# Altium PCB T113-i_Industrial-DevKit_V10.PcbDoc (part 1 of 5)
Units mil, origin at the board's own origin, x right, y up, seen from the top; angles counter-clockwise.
Board outline 4212.61 x 3188.98 mil, 4 copper layers (Top Layer, GND, PWR, Bottom Layer); 249 components, 236 nets, 911 pads, 571 vias.
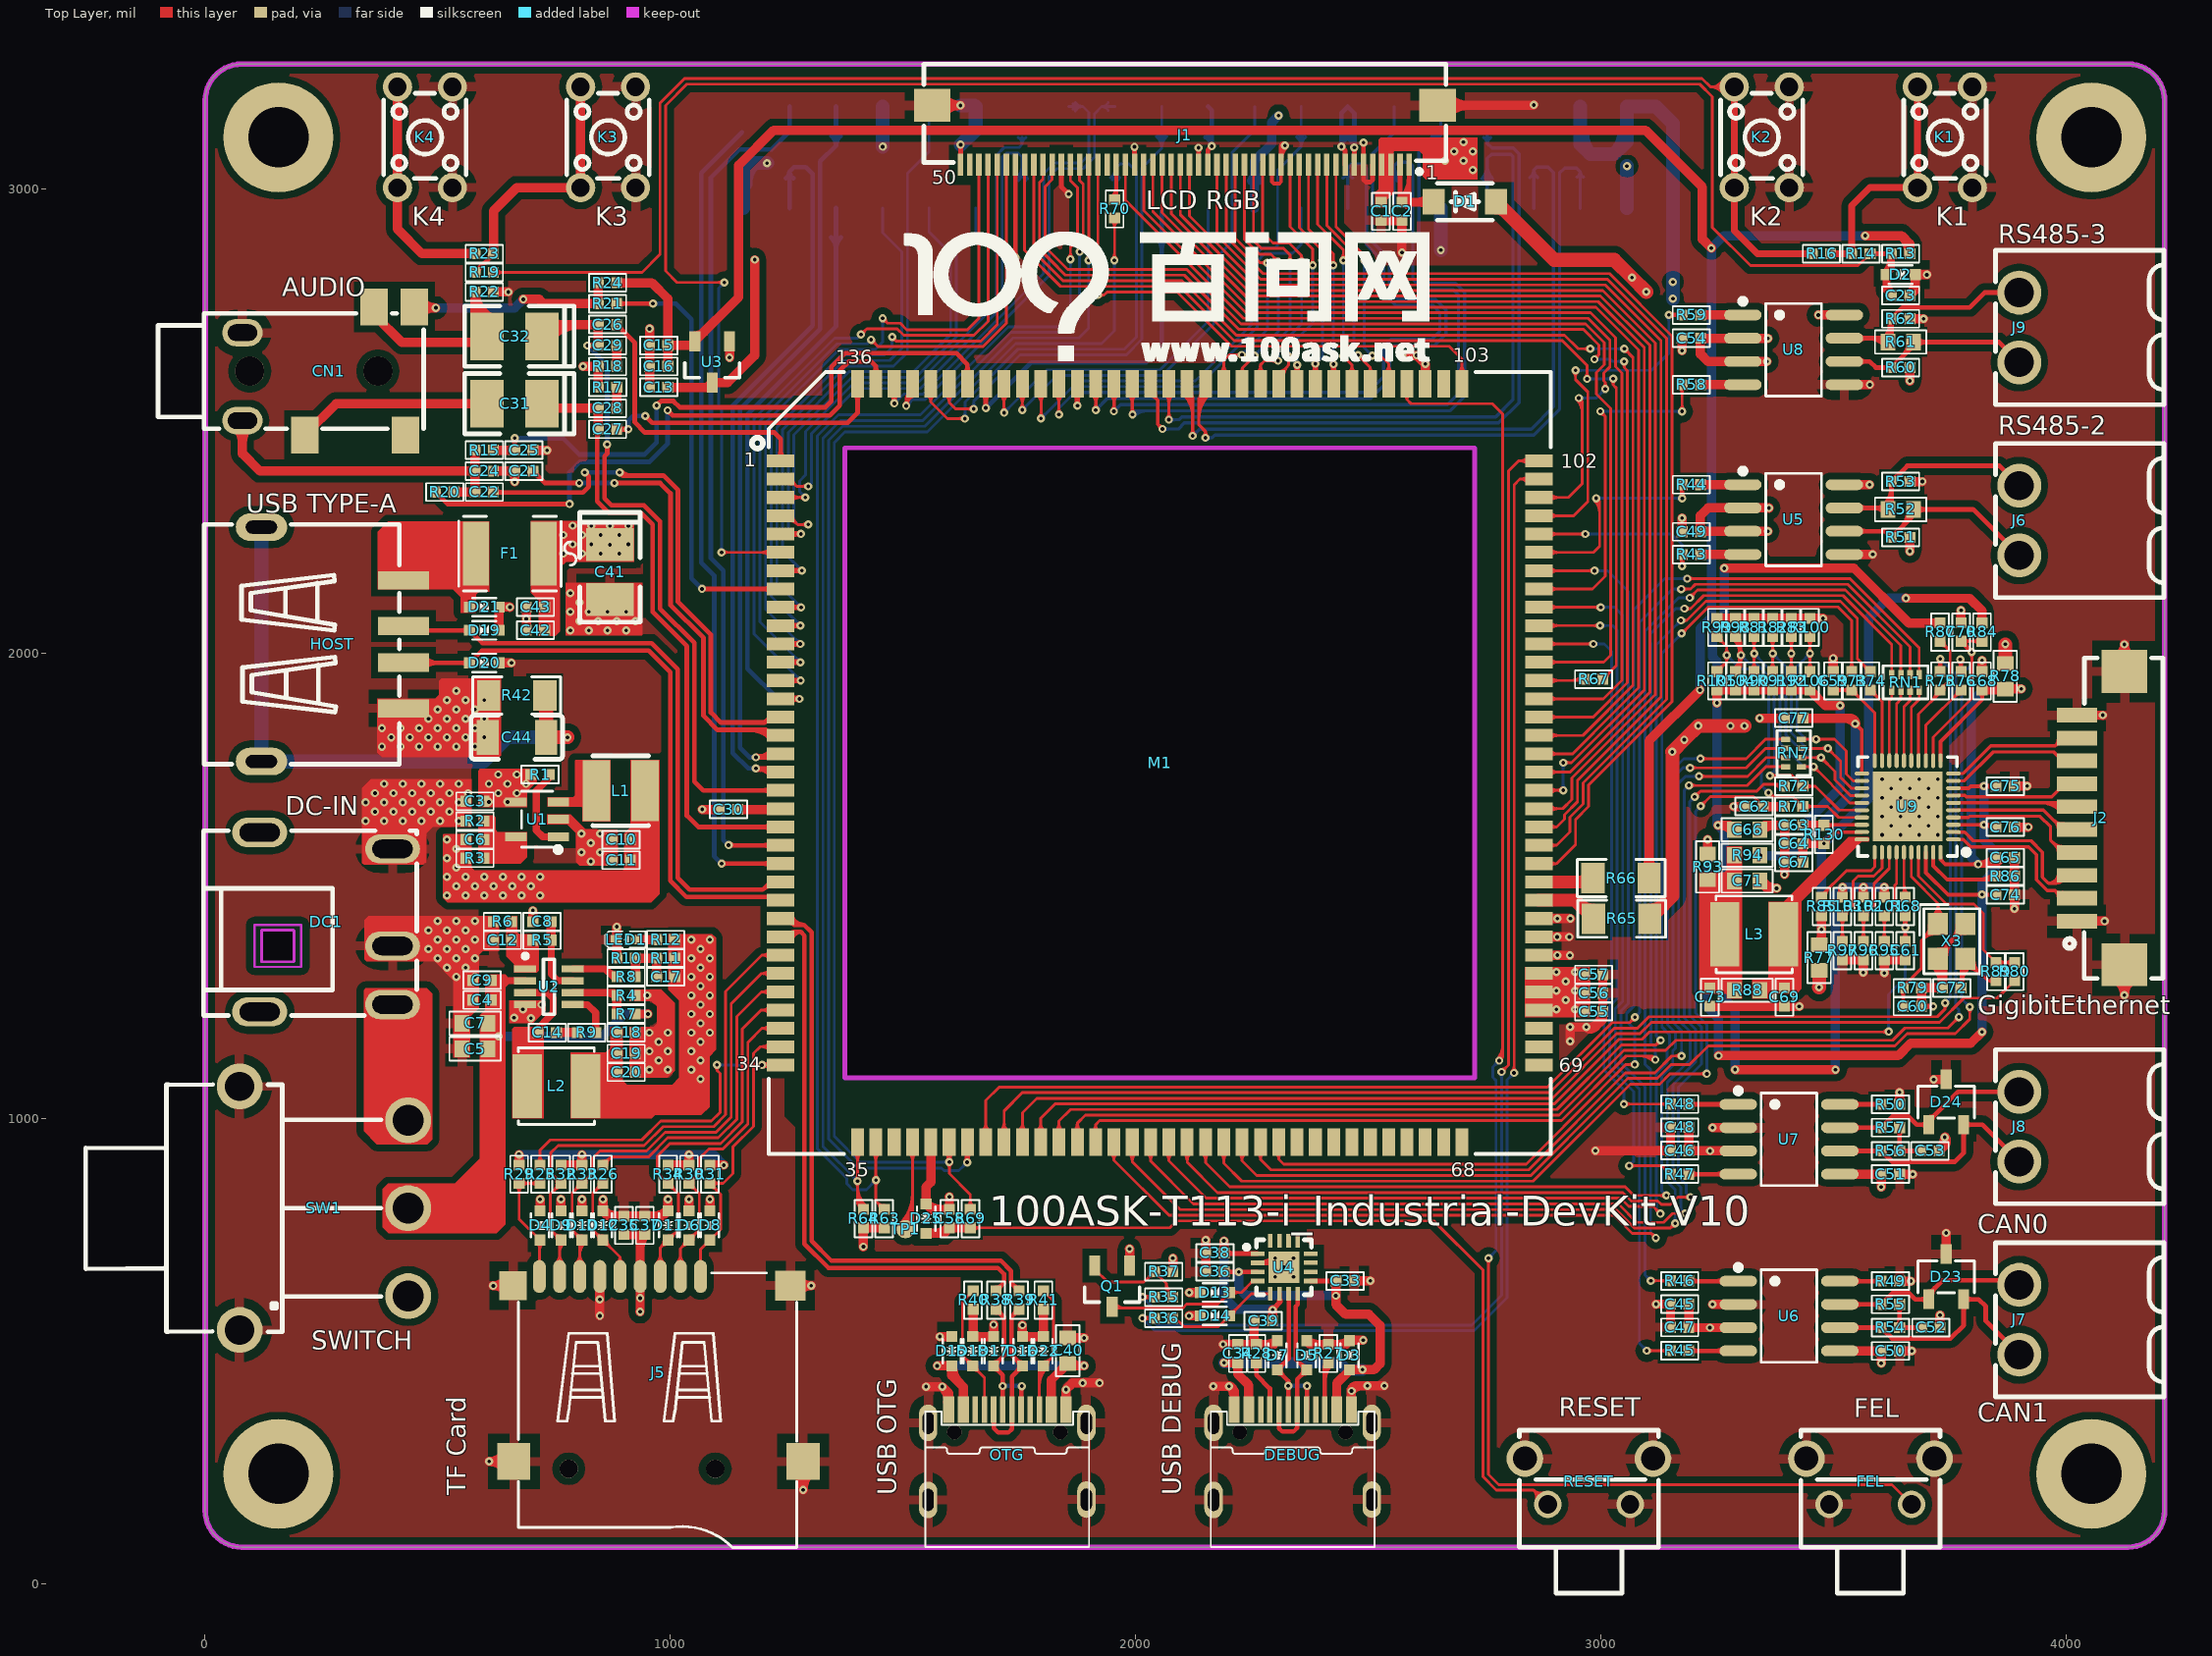
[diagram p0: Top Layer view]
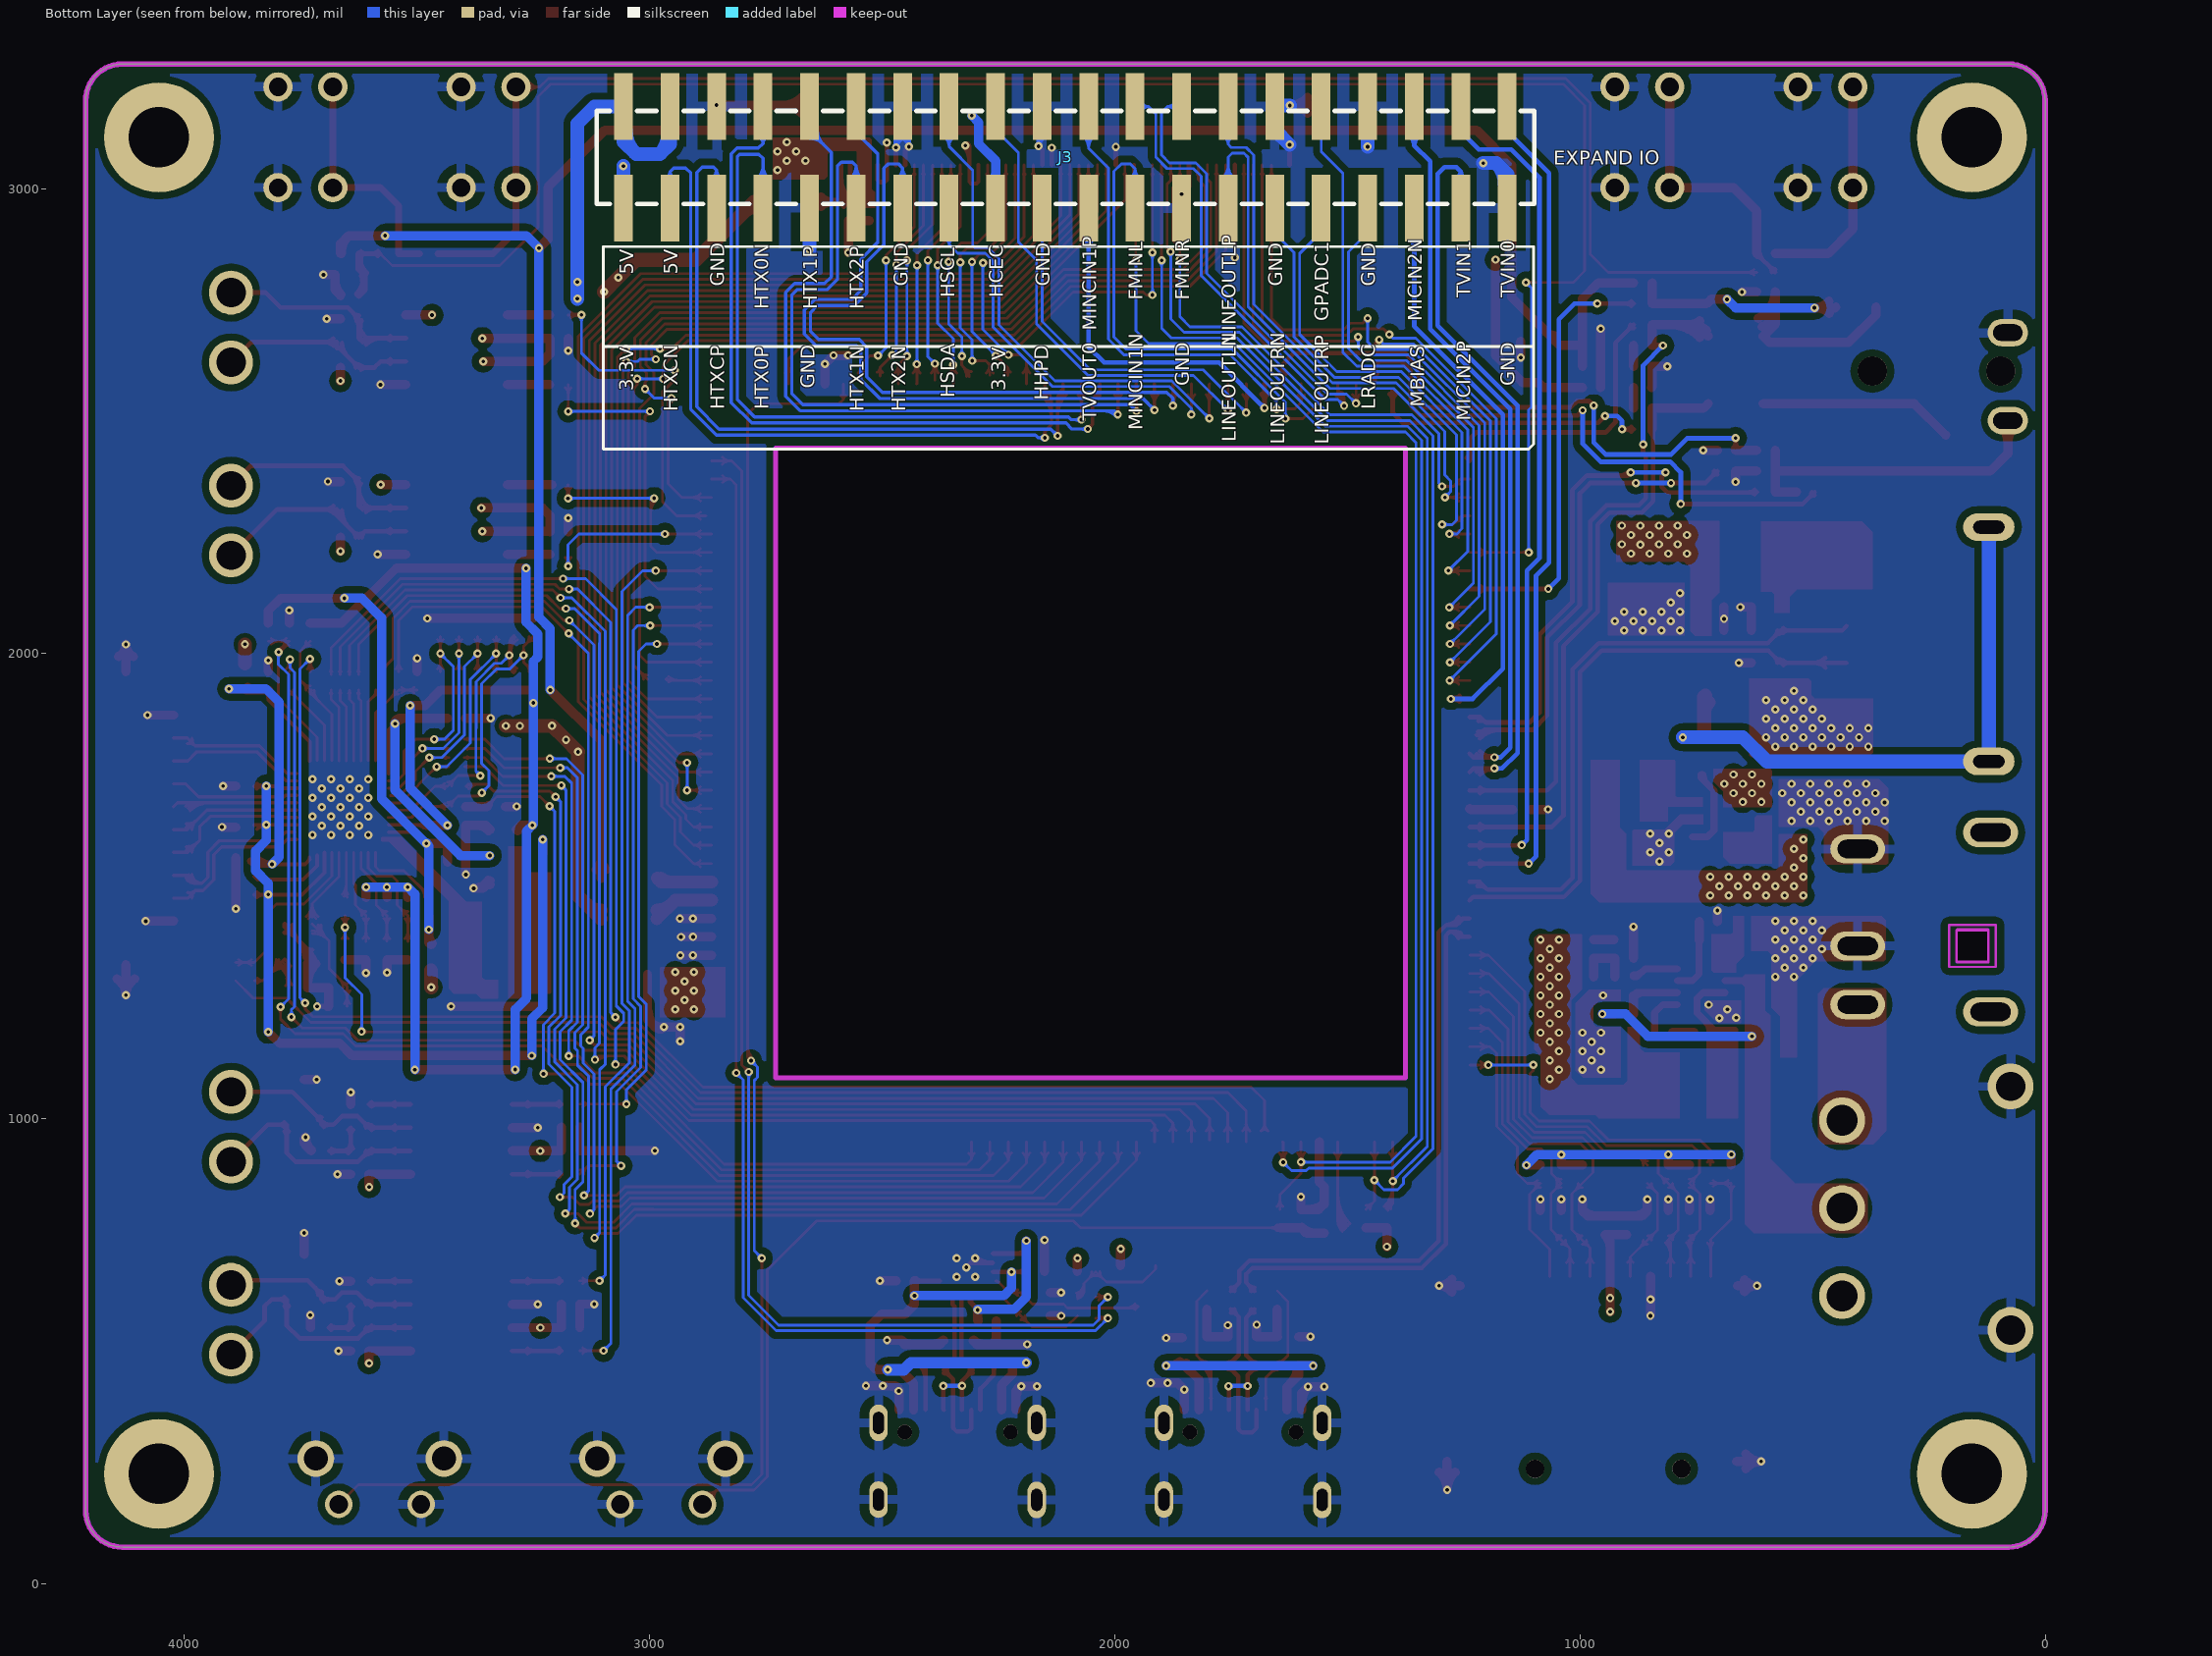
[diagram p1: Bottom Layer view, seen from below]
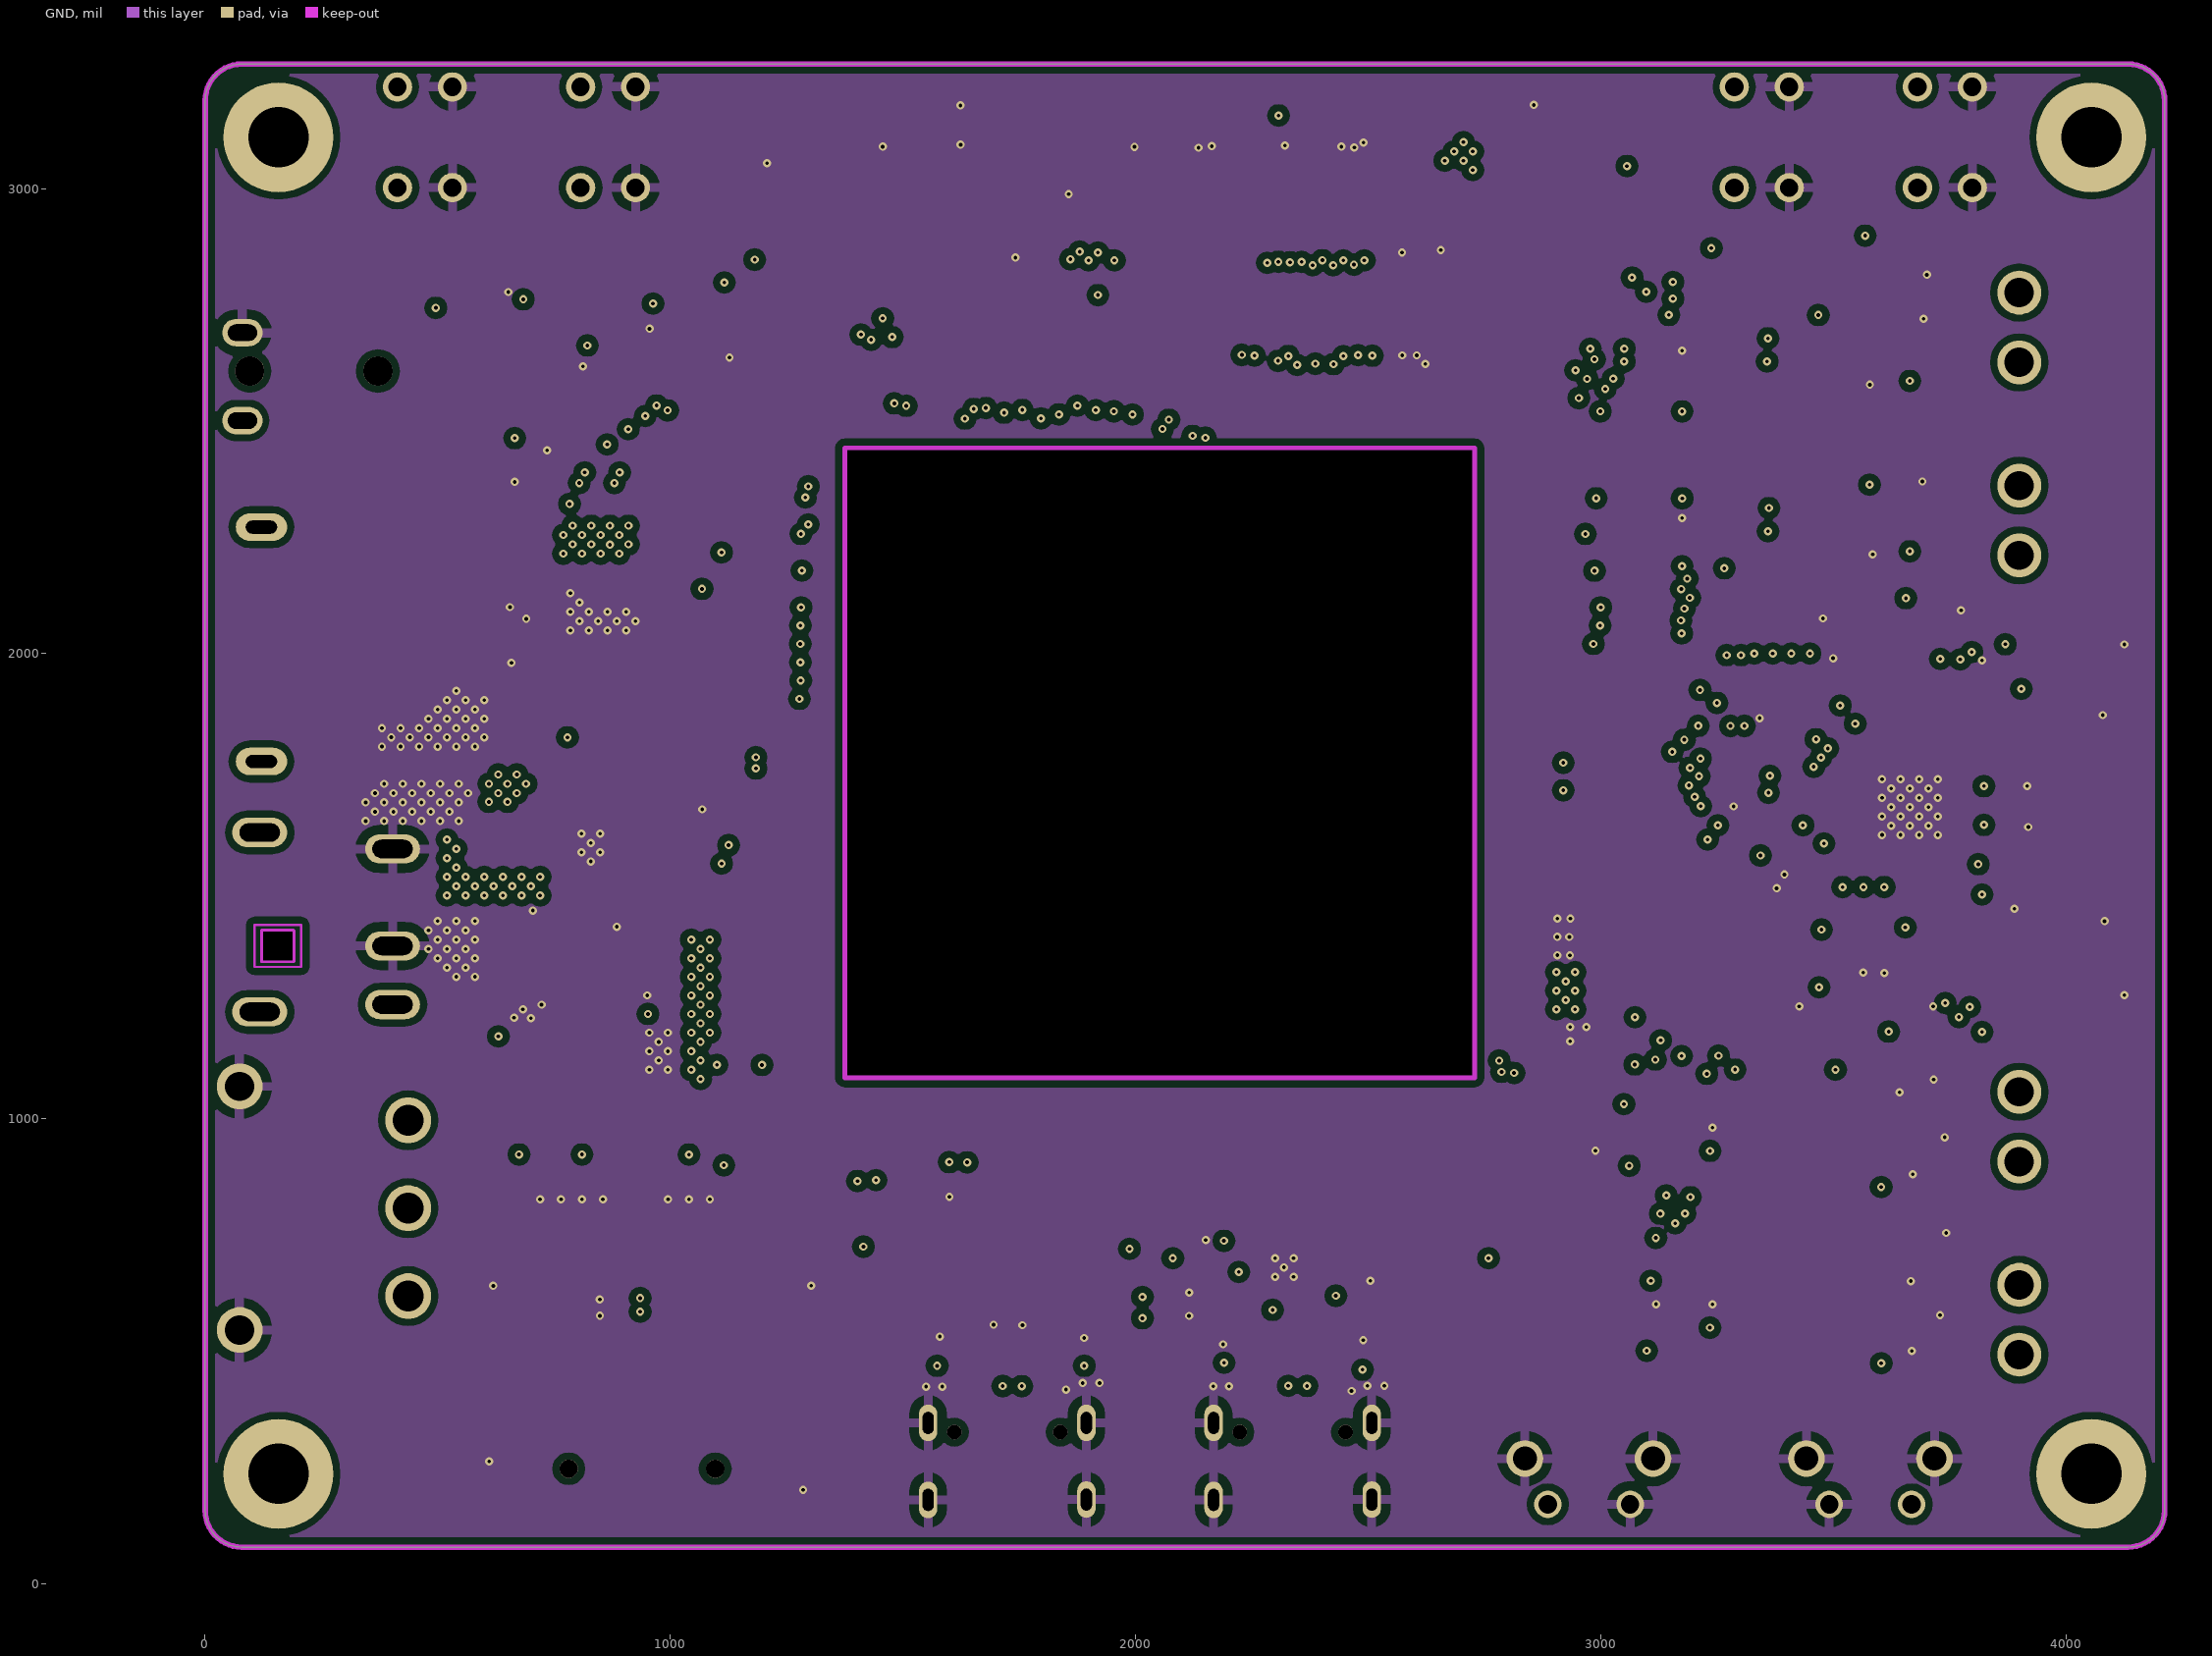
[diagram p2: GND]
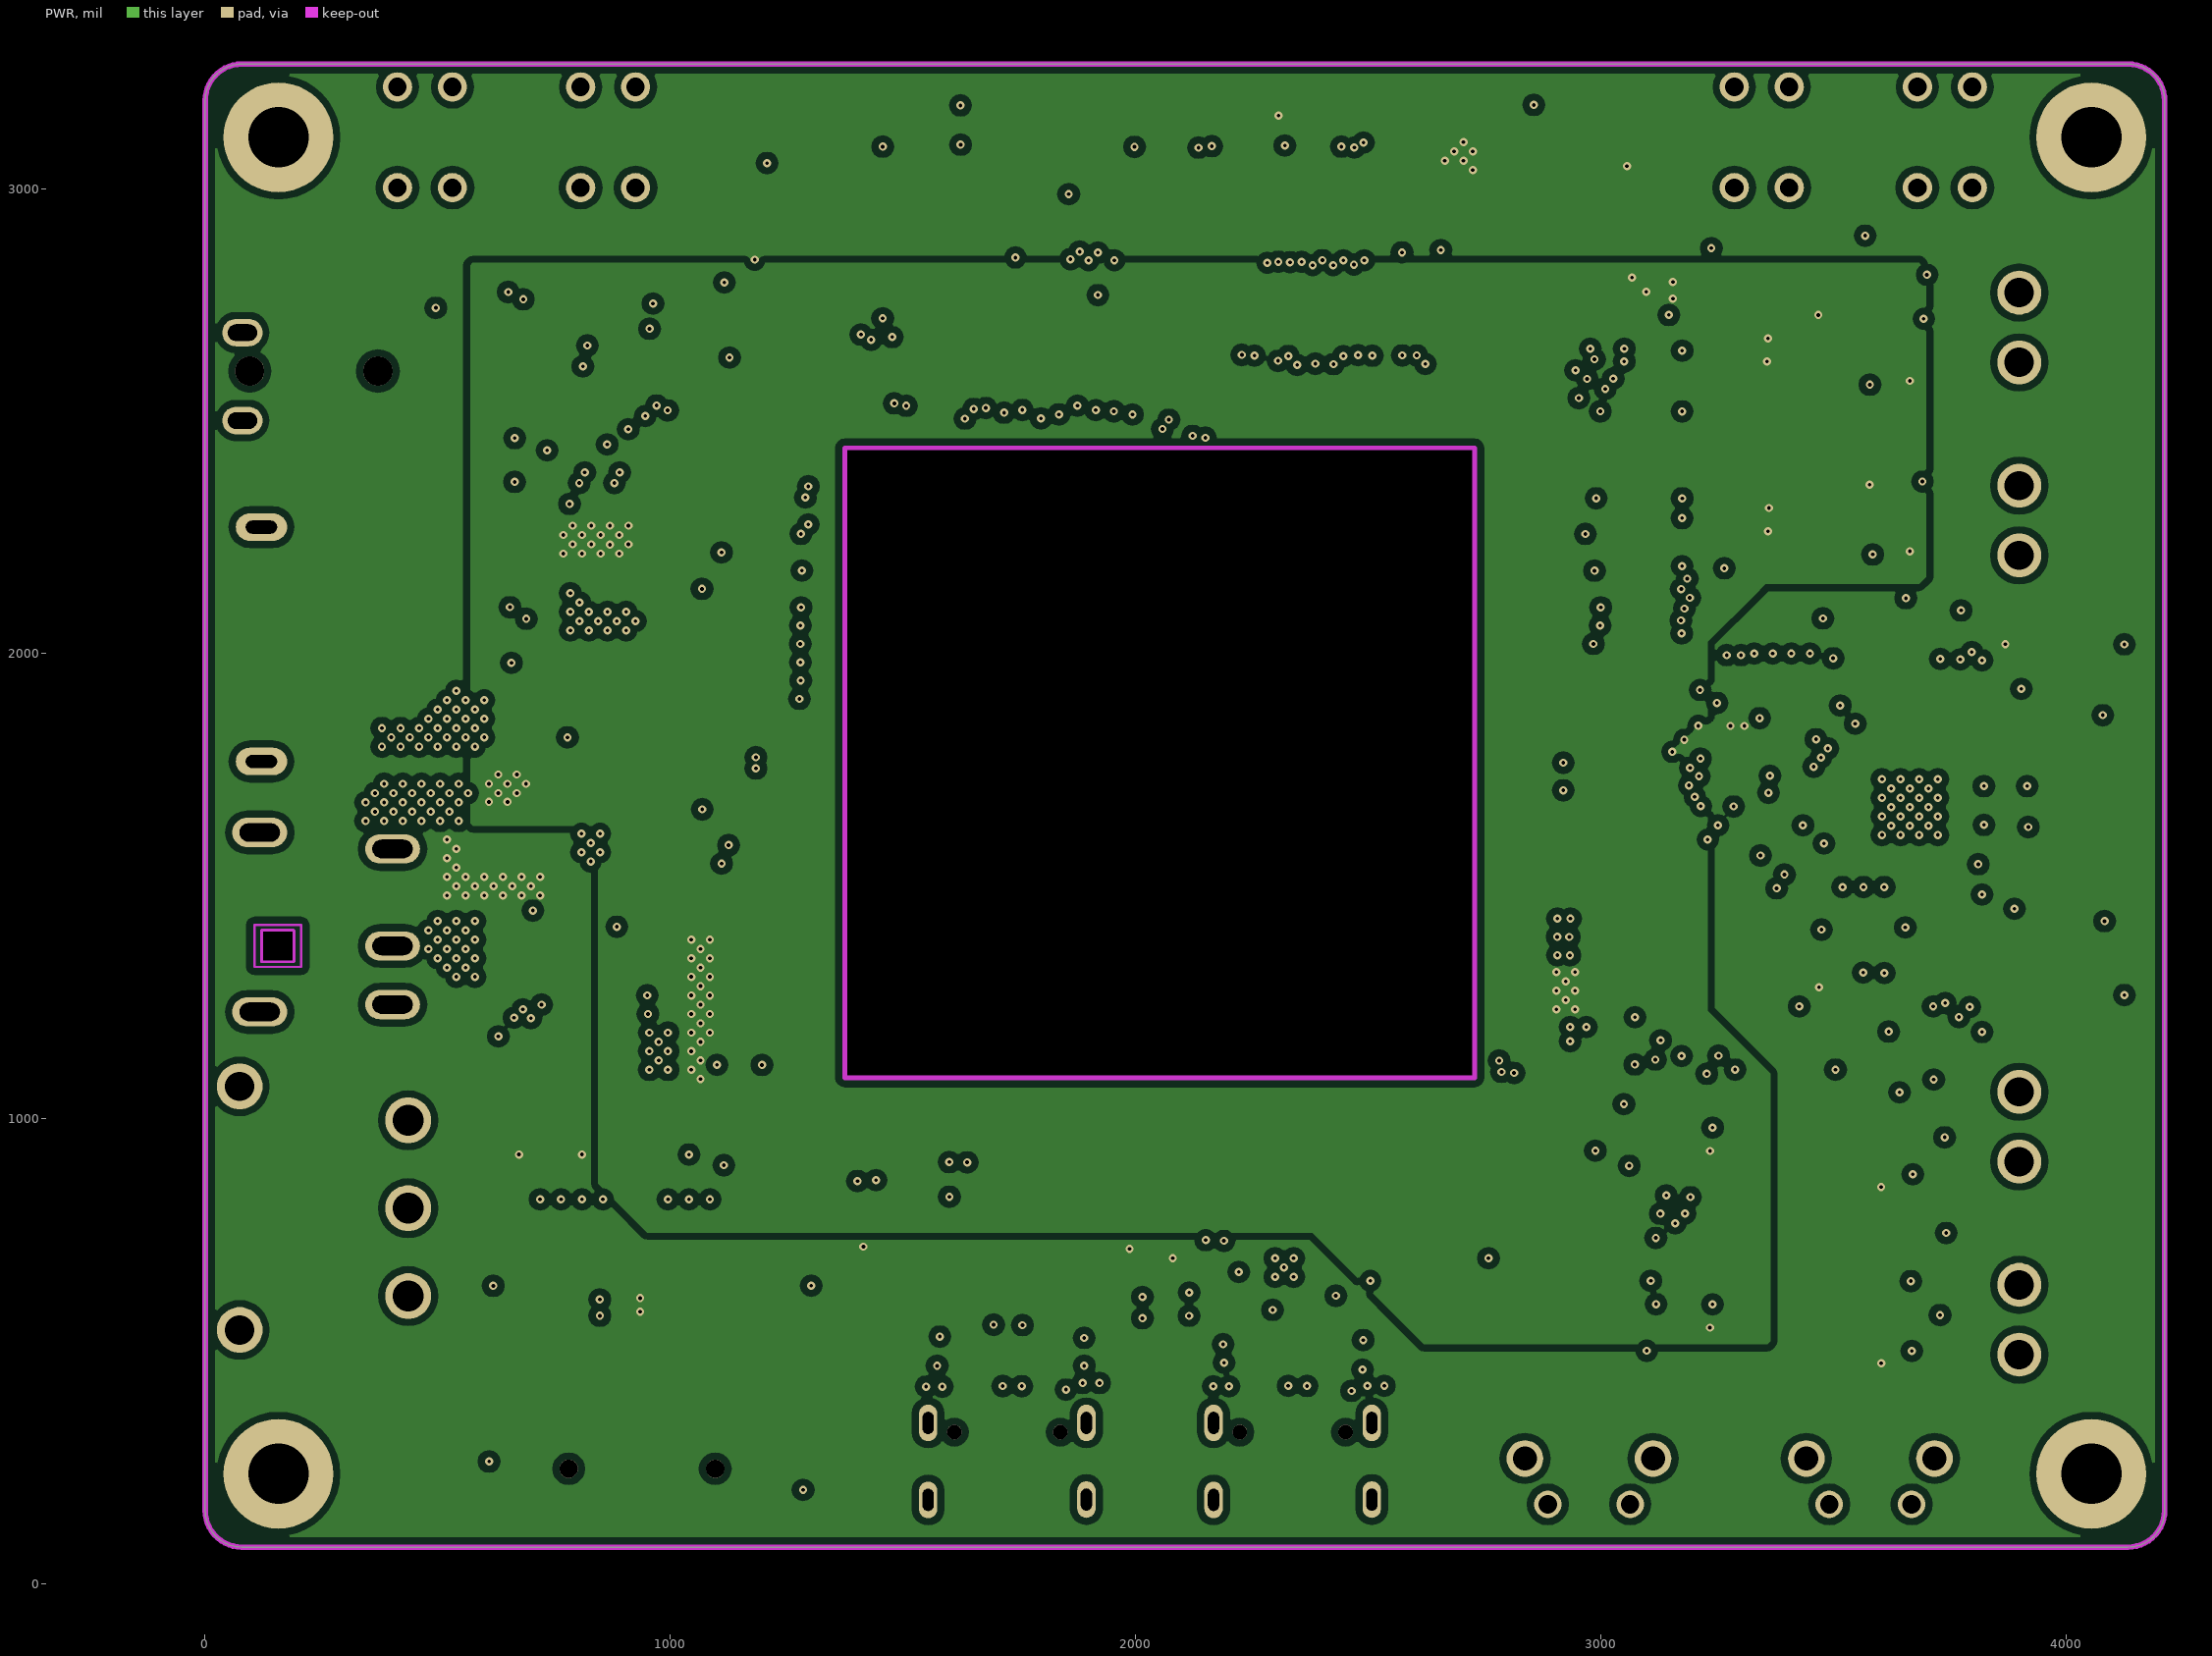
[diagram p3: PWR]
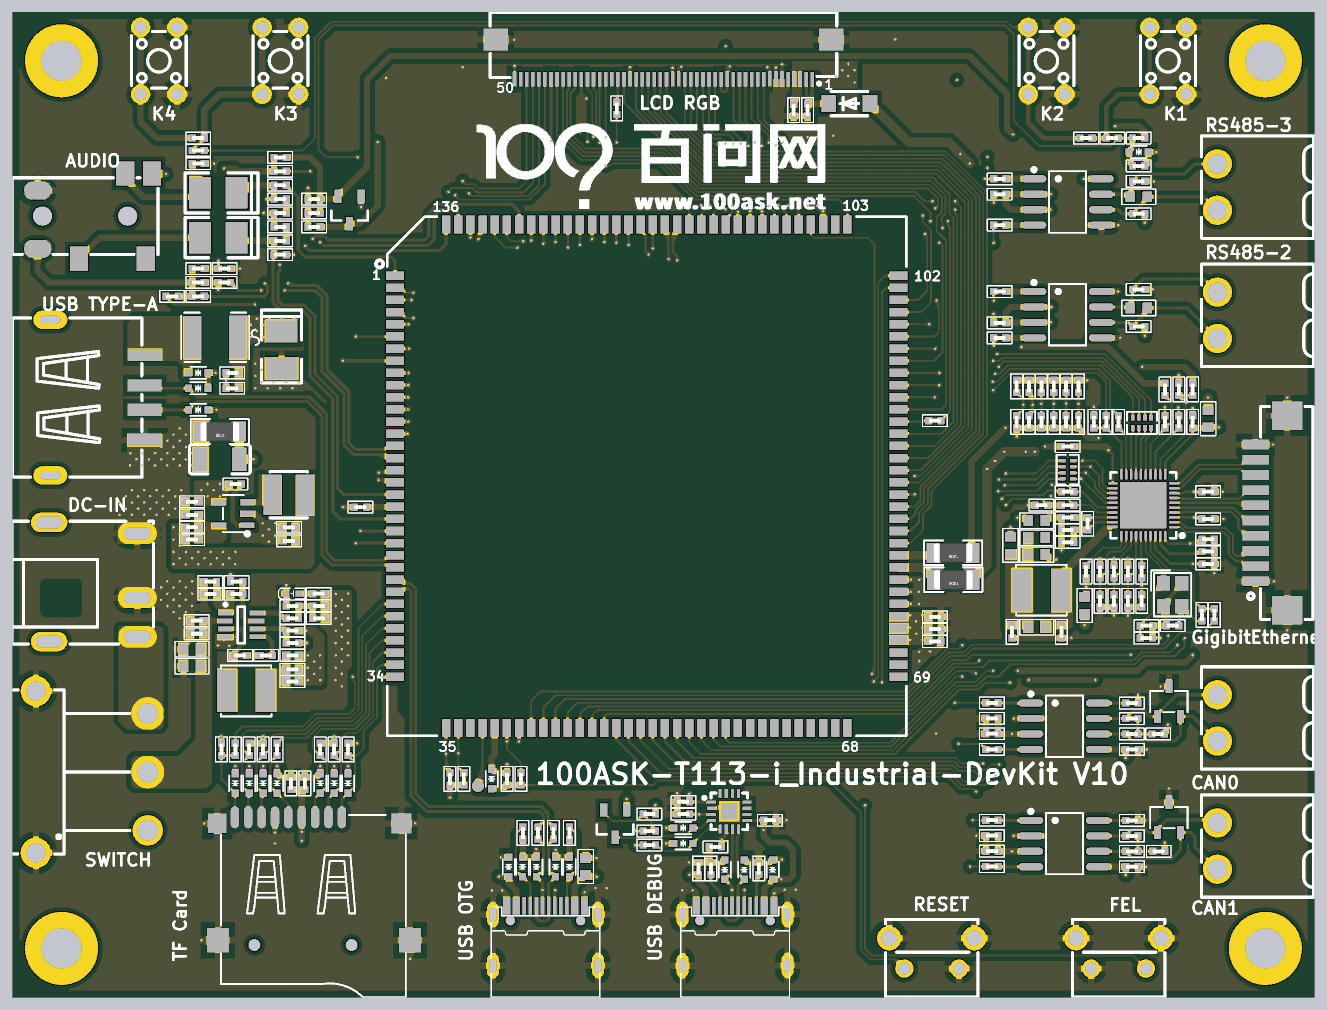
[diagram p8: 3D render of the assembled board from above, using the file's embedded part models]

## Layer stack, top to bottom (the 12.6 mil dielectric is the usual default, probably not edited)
Top Layer: signal copper 1.4
Dielectric: core 12.6, FR-4, Dk 4.8
GND: signal copper 1.4
Dielectric: prepreg 12.6, FR-4, Dk 4.8
PWR: signal copper 1.4
Dielectric: core 12.6, FR-4, Dk 4.8
Bottom Layer: signal copper 1.4

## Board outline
78.74,78.74 cw(c78.74,157.48) 0,157.48 -0.02,157.48 -0.02,3188.98 0,3188.98 cw(c78.74,3188.98) 78.74,3267.72 4133.86,3267.72 cw(c4133.86,3188.98) 4212.6,3188.98 4212.6,157.48 cw(c4133.86,157.48) 4133.86,78.74
cut-out: 1375,1087.8 1375,2442.13 2729.33,2442.13 2729.33,1087.8
cut-out: 119.69,1337.87 119.69,1404.8 cw(c122.21,1404.8) 120.7,1406.81 cw(c122.71,1405.3) 122.71,1407.81 188.64,1407.81 cw(c188.64,1405.3) 191.02,1406.1 cw(c190.22,1403.72) 192.74,1403.72 192.74,1338.95 cw(c190.22,1338.95) 190.97,1336.55 cw(c188.56,1337.3) 188.56,1334.78 122.78,1334.78 cw(c122.78,1337.3) 120.74,1335.83 cw(c122.21,1337.87)

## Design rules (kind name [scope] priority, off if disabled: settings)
Clearance Clearance_1 [InPolygon] p1: gap=15
Clearance [All] p2: gap=6
ComponentClearance [All] p1 off: gap=10 collisioncheckmode=3 verticalgap=10 showdistances=FALSE
HoleSize [All] p1: absolutevalues=TRUE maxlimit=200 minlimit=1 maxpercent=80.000 minpercent=20.000
MinimumSolderMaskSliver [All] p1 off: minsoldermaskwidth=3
PolygonConnect PolygonConnect_1 [IsVia] p1: connectstyle=Direct reliefconductorwidth=10 reliefentries=4 polygonreliefangle="90 Angle" airgapwidth=10
PolygonConnect [All] p2: connectstyle=Relief reliefconductorwidth=20 reliefentries=4 polygonreliefangle="90 Angle" airgapwidth=20
RoutingLayers [All] p1: top layer_v5=TRUE mid layer 1_v5=FALSE mid layer 2_v5=FALSE bottom layer_v5=TRUE
RoutingVias [All] p1: holewidth=7.87 width=17.72 viastyle="Through Hole" minholewidth=7.87 minwidth=17.72 maxholewidth=7.87 maxwidth=17.72
SilkToSilkClearance [All] p1 off: silktosilkclearance=10
SilkToSolderMaskClearance [IsPad] p1 off: minsilkscreentomaskgap=3 clearancetoexposedcopper=TRUE
SolderMaskExpansion [All] p1: expansion=4
Width [All] p1: maxlimit=100 minlimit=4 preferedwidth=6 minimp=50.000000 maximp=50.000000 favimp=50.000000
22 further rules are at their usual default settings.

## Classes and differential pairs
component class ETHERNET: C59 C60 C61 C62 C63 C64 C65 C66 C67 C68 C69 C70 C71 C72 C73 C74 C75 C76 C77 J2 L3 R68 R71 R72 R73 R74 R75 R76 R77 R78 R79 R80 R81 R82 R83 R84 R85 R86 R87 R88 R89 R90 R91 R92 R93 R94 R95 R96 R97 R98 R99 R100 R101 R102 R103 R104 R105 R106 R130 RN1 RN7 U9 X3
component class LCD&PWR: C1 C2 C3 C4 C5 C6 C7 C8 C9 C10 C11 C12 C13 C14 C15 C16 C17 C18 C19 C20 D1 DC1 J1 L1 L2 LED1 R1 R2 R3 R4 R5 R6 R7 R8 R9 R10 R11 R12 SW1 U1 U2 U3
component class AUDIO&KEY&EXPAND_IO: C21 C22 C23 C24 C25 C26 C27 C28 C29 C30 C31 C32 CN1 D2 J3 K1 K2 K3 K4 R13 R14 R15 R16 R17 R18 R19 R20 R21 R22 R23 R24
component class USB&TF: C33 C34 C35 C36 C37 C38 C39 C40 C41 C42 C43 C44 D3 D4 D5 D6 D7 D8 D9 D10 D11 D12 D13 D14 D15 D16 D17 D18 D19 D20 D21 D22 DEBUG F1 HOST J5 OTG Q1 R25 R26 R27 R28 R29 R30 R31 R32 R33 R34 R35 R36 R37 R38 R39 R40 R41 R42 U4
component class RS485&CAN: C45 C46 C47 C48 C49 C50 C51 C52 C53 C54 D23 D24 J6 J7 J8 J9 R43 R44 R45 R46 R47 R48 R49 R50 R51 R52 R53 R54 R55 R56 R57 R58 R59 R60 R61 R62 U5 U6 U7 U8
component class D1H_CORE_INTERFACE: C55 C56 C57 C58 D25 FEL M1 R63 R64 R65 R66 R67 R69 R70 RESET TP1

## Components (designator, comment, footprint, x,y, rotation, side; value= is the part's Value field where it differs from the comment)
C1 "10uF/10V" 0402 2528.02,2950.93 r90 top
C2 "10uF/10V" 0402 2573.02,2950.93 r90 top
C3 "4.7uF/10V" 0402 580,1682.52 r0 top
C4 "100nF" 0402 595,1255 r180 top
C5 "10uF/25V" 0603 580,1150 r180 top
C6 "20pF_NC" 0402 580,1600 r180 top
C7 "10uF/25V" 0603 580,1205 r180 top
C8 "100nF" 0402 724.08,1423.72 r180 top
C9 "100nF" 0402 595,1297.48 r180 top
C10 "10uF" 0402 894,1600 r0 top
C11 "0.1uF" 0402 894,1556 r0 top
C12 "1nF" 0402 639.08,1383.72 r180 top
C13 "0.1uF" 0402 975,2572.52 r180 top
C14 "100nF" 0402 735.32,1185 r180 top
C15 "0.1uF" 0402 975,2662.52 r180 top
C16 "10uF/6.3V" 0402 975,2617.52 r180 top
C17 "15pF" 0402 990,1305 r180 top
C18 "10uF" 0402 905,1185 r0 top
C19 "10uF" 0402 905,1140 r0 top
C20 "100nF" 0402 905,1100 r0 top
C21 "100nF" 0402 685,2392.48 r0 top
C22 "100nF" 0402 600,2347.48 r0 top
C23 "10nF" 0402 3645,2770 r0 top
C24 "33pF" 0402 600,2392.48 r0 top
C25 "2.2uF" 0402 685,2437.48 r0 top
C26 "100nF" 0402 865,2707.48 r180 top
C27 "100nF" 0402 865,2482.48 r180 top
C28 "100nF" 0402 865,2527.48 r0 top
C29 "100nF" 0402 865,2662.48 r0 top
C30 "100nF" 0402 1124.96,1665 r0 top
C31 "100uF/10V" CAP-SMD_CASE_B 665,2537.48 r0 top
C32 "100uF/10V" CAP-SMD_CASE_B 665,2682.48 r0 top
C33 "10uF/10V" 0402 2450.67,651.22 r180 top
C34 "0.1uF" 0402 2220,495 r90 top
C35 "10uF/6.3V" 0402 900.04,770.59 r90 top
C36 "1uF" 0402 2170.67,671.22 r180 top
C37 "0.1uF" 0402 945.04,770.59 r90 top
C38 "0.1uF" 0402 2170.67,711.22 r0 top
C39 "0.1uF" 0402 2274.43,565.3 r0 top
C40 "22uF/10V" 0603 1854.41,501.22 r270 top
C41 "100uF/10V" CAP-SMD_CASE_B 870,2175 r90 top
C42 "1uF/10V" 0402 710,2050 r0 top
C43 "0.1uF" 0402 710,2100 r180 top
C44 "10nF/1KV" 1206C 670,1820 r0 top
C45 "0.1uF/10V" 0402 3170,601.26 r180 top
C46 "0.1uF/10V" 0402 3170,931.26 r180 top
C47 "10uF/10V" 0402 3170,551.26 r180 top
C48 "10uF/10V" 0402 3170,981.26 r180 top
C49 "0.1uF/10V" 0402 3195,2262 r0 top
C50 "1uF/10V" 0402 3623.07,500.63 r180 top
C51 "1uF/10V" 0402 3623.07,880.63 r180 top
C52 "47nF" 0402 3710,550.63 r0 top
C53 "47nF" 0402 3708.07,930.63 r0 top
C54 "0.1uF/10V" 0402 3195,2678.15 r0 top
C55 "10uF" 0402 2985,1230 r180 top
C56 "10uF" 0402 2985,1270 r180 top
C57 "0.1uF" 0402 2985,1310 r180 top
C58 "0.1uF_NC" 0402 1600,785 r90 top
C59 "22pF_NC" 0402 3500,1941.26 r270 top
C60 "22pF" 0402 3670,1241.26 r0 top
C61 "22pF_NC" 0402 3655,1361.26 r270 top
C62 "22pF_NC" 0402 3330,1671.26 r180 top
C63 "0.1uF" 0402 3415,1631.26 r180 top
C64 "0.1uF" 0402 3415,1591.26 r180 top
C65 "0.1uF" 0402 3870,1561.26 r0 top
C66 "4.7uF/10V" 0603 3315,1621.26 r0 top
C67 "0.1uF" 0402 3415,1551.26 r180 top
C68 "0.1uF" 0402 3820,1941.26 r90 top
C69 "0.1uF_NC" 0402 3395,1261.26 r270 top
C70 "0.1uF" 0402 3775,2046.26 r90 top
C71 "4.7uF/10V" 0603 3315,1511.26 r0 top
C72 "22pF" 0402 3755,1281.26 r180 top
C73 "0.1uF" 0402 3235,1261.26 r270 top
C74 "0.1uF" 0402 3870,1481.26 r0 top
C75 "0.1uF" 0402 3870,1715 r0 top
C76 "0.1uF" 0402 3870,1627 r0 top
C77 "0.1uF" 0402 3415,1861.26 r180 top
CN1 "PJ-342E2-SMT" AUDIO-SMD_PJ-342E2-SMT 265,2607.48 r90 top
D1 "MBR120VLSFT1G" SOD-123_L2.8-W1.8-LS3.7-RD 2708.27,2971.69 r0 top
D2 "LESD5D5.0CT1G" SOD-523_L1.2-W0.8-LS1.6-BI 3645,2815 r180 top
D3 "LESD5D5.0CT1G" SOD-523_L1.2-W0.8-LS1.6-BI 2460,491.22 r270 top
D4 "LESD5D5.0CT1G" SOD-523_L1.2-W0.8-LS1.6-BI 720.04,770.59 r270 top
D5 "LESD5D5.0CT1G" SOD-523_L1.2-W0.8-LS1.6-BI 2368,491.22 r270 top
D6 "LESD5D5.0CT1G" SOD-523_L1.2-W0.8-LS1.6-BI 1040.04,770.59 r270 top
D7 "LESD5D5.0CT1G" SOD-523_L1.2-W0.8-LS1.6-BI 2305,491.22 r270 top
D8 "LESD5D5.0CT1G" SOD-523_L1.2-W0.8-LS1.6-BI 1085.04,770.59 r270 top
D9 "LESD5D5.0CT1G" SOD-523_L1.2-W0.8-LS1.6-BI 765.04,770.59 r270 top
D10 "LESD5D5.0CT1G" SOD-523_L1.2-W0.8-LS1.6-BI 810.04,770.59 r270 top
D11 "LESD5D5.0CT1G" SOD-523_L1.2-W0.8-LS1.6-BI 995.04,770.59 r270 top
D12 "LESD5D5.0CT1G" SOD-523_L1.2-W0.8-LS1.6-BI 855.04,770.59 r270 top
D13 "LESD5D5.0CT1G" SOD-523_L1.2-W0.8-LS1.6-BI 2170.67,626.22 r180 top
D14 "LESD5D5.0CT1G" SOD-523_L1.2-W0.8-LS1.6-BI 2170.67,576.22 r180 top
D15 "LESD5D5.0CT1G" SOD-523_L1.2-W0.8-LS1.6-BI 1605,500 r270 top
D16 "LESD5D5.0CT1G" SOD-523_L1.2-W0.8-LS1.6-BI 1757,500 r270 top
D17 "LESD5D5.0CT1G" SOD-523_L1.2-W0.8-LS1.6-BI 1695,500 r270 top
D18 "LESD5D5.0CT1G" SOD-523_L1.2-W0.8-LS1.6-BI 1650,500 r270 top
D19 "LESD5D5.0CT1G" SOD-523_L1.2-W0.8-LS1.6-BI 600,2050 r180 top
D20 "LESD5D5.0CT1G" SOD-523_L1.2-W0.8-LS1.6-BI 600,1980 r180 top
D21 "LESD5D5.0CT1G" SOD-523_L1.2-W0.8-LS1.6-BI 600,2100 r180 top
D22 "LESD5D5.0CT1G" SOD-523_L1.2-W0.8-LS1.6-BI 1802,500 r270 top
D23 "PESD1CAN" SOT-23-3_L2.9-W1.6-P1.90-LS2.8-BR 3743.07,660 r270 top
D24 "PESD1CAN" SOT-23-3_L2.9-W1.6-P1.90-LS2.8-BR 3743.07,1035.63 r270 top
D25 "LESD5D5.0CT1G" SOD-523_L1.2-W0.8-LS1.6-BI 1550,785 r270 top
DC1 "DC-044A-A200" DC-IN-TH_DC-044A-20A 260,1422.52 r0 top locked (schematic designator U1)
DEBUG "U262-16XN-4BVC11" "TYPEC-12PIN - duplicate" 2338,181.22 r0 top
F1 "SMD1812P100TF" F1812 655,2215 r180 top
FEL "TC-6615-6-260G" KEY-TH_TC-6615-6-160G 3580,220 r0 top
HOST "912-121A2026S10100 TYPE-A座" USB-A-TH_C42425 273.76,2020 r270 top
J1 "myir_LCD_port" FPC-SMD_50P-P0.50_FPC-05FB-50PH20_MIRROR 2106.3,3115 r180 top (schematic designator J2)
J2 "HC-1.25-10PWT" CONN-SMD_10P-P1.25_HCTL_HC-1.25-10PWT 4075,1646.26 r90 top
J3 "2*20P,2.54毫米间距双排插针" HDR-SMD_40P-P2.54-V-M-R2-C20-LS7.5 2106.3,3067 r180 bottom locked
J5 "SD_MR01A_01211" SD-MR01A-01211 972.52,369.25 r0 top locked
J6 "KF2EDGR-3.81-2P" CONN-TH_2P-P3.81_KF2EDGR-3.81-2P 3900,2286.26 r90 top
J7 "KF2EDGR-3.81-2P" CONN-TH_2P-P3.81_KF2EDGR-3.81-2P 3900,567.63 r90 top
J8 "KF2EDGR-3.81-2P" CONN-TH_2P-P3.81_KF2EDGR-3.81-2P 3900,982.63 r90 top
J9 "KF2EDGR-3.81-2P" CONN-TH_2P-P3.81_KF2EDGR-3.81-2P 3900,2701.26 r90 top
K1 "TS-1009-03826" SW-TH_4P-L4.5-W4.5-P3.00-LS5.5 3740.16,3110.24 r90 top
K2 "TS-1009-03826" SW-TH_4P-L4.5-W4.5-P3.00-LS5.5 3346.46,3110.24 r90 top
K3 "TS-1009-03826" SW-TH_4P-L4.5-W4.5-P3.00-LS5.5 866.14,3110.24 r90 top
K4 "TS-1009-03826" SW-TH_4P-L4.5-W4.5-P3.00-LS5.5 472.44,3110.24 r90 top
L1 "SWPA3015S2R2MT" IND-SMD_L3.0-W3.0 893,1705 r180 top
L2 "WPN4020H4R7MT" IND-SMD_L4.0-W4.0 755,1070 r0 top
L3 "CR4018-2R2M" IND-SMD_L4.0-W4.0 3330,1396.26 r180 top
LED1 "RedLED" LED0402 905,1385 r0 top
M1 "D1H_STAMP_CORE" D1H_STAMP_CORE 2052.17,1764.96 r0 top locked
OTG "U262-16XN-4BVC11" "TYPEC-12PIN - duplicate" 1724.37,181.22 r0 top
Q1 "AO 3400" SOT23 1950,640 r270 top
R1 "100K" 0402 720,1740 r180 top
R2 "100K" 0402 580,1640 r180 top
R3 "453K" 0402 580,1560 r0 top
R4 "51K_NC" 0402 905,1265 r0 top
R5 "100K" 0402 724.08,1383.72 r0 top
R6 "10K" 0402 639.08,1423.72 r180 top
R7 "56K" 0402 905,1225 r180 top
R8 "15K" 0402 905,1305 r180 top
R9 "10R" 0402 820,1185 r0 top
R10 "8.25K" 0402 905,1345 r180 top
R11 "43.2K" 0402 990,1345 r180 top
R12 "2.2K" 0402 990,1385 r0 top
R13 "51K" 0402 3645,2860 r0 top
R14 "6.8K" 0402 3559.68,2860 r0 top
R15 "2K" 0402 600,2437.48 r0 top
R16 "8.2K" 0402 3474.68,2860 r0 top
R17 "22R" 0402 865.32,2572.48 r180 top
R18 "22R" 0402 865,2617.48 r180 top
R19 "10K" 0402 600,2820 r0 top
R20 "1K" 0402 515,2347.48 r180 top
R21 "1K" 0402 865,2752.48 r0 top
R22 "100K" 0402 600,2777.52 r180 top
R23 "11K" 0402 600,2860 r0 top
R24 "1M" 0402 865,2797.48 r0 top
R25 "22R" 0402 720.04,880.59 r90 top
R26 "33R" 0402 855.04,880.59 r90 top
R27 "5.1K" 0402 2415,495 r90 top
R28 "5.1K" 0402 2260,495 r90 top
R29 "10K" 0402 675.04,880.59 r270 top
R30 "47K" 0402 1040.04,880.59 r270 top
R31 "47K" 0402 1085.04,880.59 r270 top
R32 "47K" 0402 765.04,880.59 r270 top
R33 "47K" 0402 810.04,880.59 r270 top
R34 "10K" 0402 995.04,880.59 r270 top
R35 "33R" 0402 2060.67,616.22 r0 top
R36 "1K" 0402 2060.67,571 r0 top
R37 "10K" 0402 2060.67,671.22 r180 top
R38 "22R" 0402 1700,610 r90 top
R39 "22R" 0402 1750,610 r90 top
R40 "10K" 0402 1651,610 r90 top
R41 "10K" 0402 1802,610 r90 top
R42 "0R" 1206R 670,1910 r0 top
R43 "22R" 0402 3195,2213.15 r0 top
R44 "22R" 0402 3195,2363.15 r0 top
R45 "22R" 0402 3170,501.26 r180 top
R46 "22R" 0402 3170,651.26 r180 top
R47 "22R" 0402 3170,880.63 r180 top
R48 "22R" 0402 3170,1031.26 r180 top
R49 "4.7K" 0402 3623.07,650.63 r180 top
R50 "4.7K" 0402 3623.07,1030.63 r180 top
R51 "10K" 0402 3645,2250 r180 top
R52 "120R" 0603 3645,2310 r180 top
R53 "10K" 0402 3645,2370 r0 top
R54 "60.4R" 0402 3623.07,550.63 r0 top
R55 "60.4R" 0402 3623.07,600.63 r180 top
R56 "60.4R" 0402 3623.07,930.63 r0 top
R57 "60.4R" 0402 3623.07,980.63 r180 top
R58 "22R" 0402 3195,2578.15 r0 top
R59 "22R" 0402 3195,2728.15 r0 top
R60 "2K" 0402 3645,2615 r180 top
R61 "120R" 0603 3645,2670 r180 top
R62 "2K" 0402 3645,2720 r0 top
R63 "10K" 0402 1460,785 r270 top
R64 "10K" 0402 1415,785 r270 top
R65 "0R_NC" 1206R 3045,1430 r0 top
R66 "0R_NC" 1206R 3044.01,1517.19 r0 top
R67 "33R" 0402 2985,1945 r180 top
R68 "0R" 0402 3655,1456.26 r270 top
R69 "470R" 0402 1645,785 r90 top
R70 "0R" 0402 1955,2956.26 r90 top
R71 "0R" 0402 3415,1671.26 r180 top
R72 "0R" 0402 3415,1715 r180 top
R73 "0R" 0402 3540,1941.26 r90 top
R74 "0R" 0402 3580,1941.26 r90 top
R75 "0R" 0402 3730,1941.26 r90 top
R76 "0R" 0402 3775,1941.26 r90 top
R77 "0.01R,1%" 0603 3470,1346.26 r270 top
R78 "0.01R,1%" 0603 3870,1951.26 r90 top
R79 "0R_NC" 0402 3670,1281.26 r0 top
R80 "0R_NC" 0402 3890,1316.26 r270 top
R81 "4.7K_NC" 0402 3330,2056.26 r90 top
R82 "4.7K" 0402 3370,2056.26 r90 top
R83 "4.7K" 0402 3410,2056.26 r90 top
R84 "4.7K" 0402 3820,2046.26 r90 top
R85 "4.7K" 0402 3475,1456.26 r270 top
R86 "2.49K,1%" 0402 3870,1521.26 r0 top
R87 "1.5K" 0402 3730,2046.26 r90 top
R88 "0R_NC" 0603 3315,1276.26 r0 top
R89 "0R" 0402 3850,1316.26 r90 top
R90 "4.7K" 0402 3330,1941.26 r90 top
R91 "4.7K_NC" 0402 3370,1941.26 r90 top
R92 "4.7K_NC" 0402 3410,1941.26 r90 top
R93 "0R" 0603 3230,1541.26 r270 top
R94 "0R" 0603 3315,1566.26 r180 top
R95 "4.7K" 0402 3610,1361.26 r270 top
R96 "4.7K" 0402 3565,1361.26 r270 top
R97 "4.7K_NC" 0402 3520,1361.26 r270 top
R98 "4.7K" 0402 3290,2056.26 r90 top
R99 "4.7K" 0402 3250,2056.26 r90 top
R100 "4.7K_NC" 0402 3450,2056.26 r90 top
R101 "4.7K_NC" 0402 3610,1456.26 r270 top
R102 "4.7K_NC" 0402 3565,1456.26 r270 top
R103 "4.7K" 0402 3520,1456.26 r270 top
R104 "4.7K_NC" 0402 3290,1941.26 r90 top
R105 "4.7K_NC" 0402 3250,1941.26 r90 top
R106 "4.7K" 0402 3450,1941.26 r90 top
R130 "0R" 0402 3480,1611.26 r270 top
RESET "TC-6615-6-260G" KEY-TH_TC-6615-6-160G 2975,220 r0 top
RN1 "22R" RES-ARRAY-SMD_0402-8P-L2.0-W1.0-BL 3655.47,1938.09 r180 top
RN7 "22R" RES-ARRAY-SMD_0402-8P-L2.0-W1.0-BL 3415,1786.26 r270 top
SW1 "SS-12D11G3R" SW-TH_SS-12D11L3 255.31,807.52 r90 top
TP1 "Value" TP_1MM 1505.6,762.37 r0 top
U1 "SY8089A1AAC" SOT-23-5_L3.0-W1.7-P0.95-LS2.8-BL 713.66,1643.76 r90 top
U2 "MP1495S" TSOT-23-8 739.08,1283.72 r0 top
U3 "XC6206P182MR" SOT23 1090,2627.52 r270 top
U4 "CH343P" TQFN-16_L3.0-W3.0-P0.50-BL-EP1.7 2319.43,680.31 r270 top
U5 "MAX13487EESA+" SOIC-8_L4.9-W3.9-P1.27-LS6.0-BL 3415,2288.15 r270 top
U6 "TJA1042T/3/1J" SOIC-8_L4.9-W3.9-P1.27-LS6.0-BL 3405,575.63 r270 top (schematic designator U7)
U7 "TJA1042T/3/1J" SOIC-8_L4.9-W3.9-P1.27-LS6.0-BL 3405,955.63 r270 top
U8 "MAX13487EESA+" SOIC-8_L4.9-W3.9-P1.27-LS6.0-BL 3415,2653.15 r270 top
U9 "RTL8211F-CG" WQFN-40_L5.0-W5.0-P0.4-BL-EP 3660,1671.26 r90 top
X3 "25MHz" OSC-SMD_4P-L2.5-W2.0-BL 3755,1381.26 r270 top

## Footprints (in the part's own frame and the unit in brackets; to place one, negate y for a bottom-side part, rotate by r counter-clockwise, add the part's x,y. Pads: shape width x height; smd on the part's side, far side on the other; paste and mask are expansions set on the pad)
0402 [mm]
  rect 0.6x0.6 smd: 1(-0.5,0) 2(0.5,0)
  silkscreen extent -1.02,-0.48 1.02,0.48, body extent -0.51,-0.18 0.49,0.18, height 0.27
0603 [mm] "Chip Capacitor, Body 1.6x0.8mm, IPC High Density"
  rect 0.8x0.9 smd: 1(-0.7,0) 2(0.7,0)
  silkscreen extent -1.4,-0.64 1.4,0.64, body extent -0.87,-0.48 0.87,0.48, height 1.3
1206C [mm]
  rect 1.2x1.9 smd: 1(-1.6,0) 2(1.6,0)
  silkscreen extent -2.5,-1.2 2.5,1.2
1206R [mm]
  rect 1.27x1.65 smd: 1(-1.53,0) 2(1.53,0)
  silkscreen extent -2.4,-1.02 2.4,1.02, body extent -1.6,-0.8 1.6,0.8, height 1
AUDIO-SMD_PJ-342E2-SMT [mm]
  oval 1.5x2.2 hole 0.9 slot 1.6 at 90 deg: 1(-2.7,4.7) 2(2.1,4.7)
  rect 2x1.5 smd: 3(-3.5,1.3) 4(3.5,-2.5) 5(3.5,-4.7) 6(-3.5,-4.2)
  round 1.6 hole 1.6 unplated: ""(0,4.3) ""(0,-2.7)
  silkscreen extent -3.15,-5.2 3.15,9.3
CAP-SMD_CASE_B [mm]
  rect 1.8x2.6 smd: 1(1.501,0) 2(-1.501,0)
  silkscreen extent -2.73,-1.65 3.26,1.65
CONN-SMD_10P-P1.25_HCTL_HC-1.25-10PWT [mm]
  rect 0.8x2.2 smd paste+0 mask+0.05: 1(-5.625,1.3) 2(-4.375,1.3) 3(-3.125,1.3) 4(-1.875,1.3) 5(-0.625,1.3) 6(0.625,1.3) 7(1.875,1.3) 8(3.125,1.3) 9(4.375,1.3) 10(5.625,1.3)
  rect 2.35x2.5 smd paste+0 mask+0.05: 11(8.005,-1.3) 12(-8.005,-1.3)
  silkscreen extent -8.75,-3.4 8.75,1.95
CONN-TH_2P-P3.81_KF2EDGR-3.81-2P [mm]
  round 2.4 hole 1.6: 1(-1.905,0) 2(1.905,0)
  silkscreen extent -4.21,-7.9 4.21,1.3
D1H_STAMP_CORE [mm]
  rect 1.5x0.7 smd: 1(-20.7,16.5) 2(-20.7,15.5) 3(-20.7,14.5) 4(-20.7,13.5) 5(-20.7,12.5) 6(-20.7,11.5) 7(-20.7,10.5) 8(-20.7,9.5) 9(-20.7,8.5) 10(-20.7,7.5) 11(-20.7,6.5) 12(-20.7,5.5) 13(-20.7,4.5) 14(-20.7,3.5) 15(-20.7,2.5) 16(-20.7,1.5) 17(-20.7,0.5) 18(-20.7,-0.5) 19(-20.7,-1.5) 20(-20.7,-2.5) 21(-20.7,-3.5) 22(-20.7,-4.5) 23(-20.7,-5.5) 24(-20.7,-6.5) 25(-20.7,-7.5) 26(-20.7,-8.5) 27(-20.7,-9.5) 28(-20.7,-10.5) 29(-20.7,-11.5) 30(-20.7,-12.5) 31(-20.7,-13.5) 32(-20.7,-14.5) 33(-20.7,-15.5) 34(-20.7,-16.5) 69(20.7,-16.5) 70(20.7,-15.5) 71(20.7,-14.5) 72(20.7,-13.5) 73(20.7,-12.5) 74(20.7,-11.5) 75(20.7,-10.5) 76(20.7,-9.5) 77(20.7,-8.5) 78(20.7,-7.5) 79(20.7,-6.5) 80(20.7,-5.5) 81(20.7,-4.5) 82(20.7,-3.5) 83(20.7,-2.5) 84(20.7,-1.5) 85(20.7,-0.5) 86(20.7,0.5) 87(20.7,1.5) 88(20.7,2.5) 89(20.7,3.5) 90(20.7,4.5) 91(20.7,5.5) 92(20.7,6.5) 93(20.7,7.5) 94(20.7,8.5) 95(20.7,9.5) 96(20.7,10.5) 97(20.7,11.5) 98(20.7,12.5) 99(20.7,13.5) 100(20.7,14.5) 101(20.7,15.5) 102(20.7,16.5)
  rect 0.7x1.5 smd: 35(-16.5,-20.7) 36(-15.5,-20.7) 37(-14.5,-20.7) 38(-13.5,-20.7) 39(-12.5,-20.7) 40(-11.5,-20.7) 41(-10.5,-20.7) 42(-9.5,-20.7) 43(-8.5,-20.7) 44(-7.5,-20.7) 45(-6.5,-20.7) 46(-5.5,-20.7) 47(-4.5,-20.7) 48(-3.5,-20.7) 49(-2.5,-20.7) 50(-1.5,-20.7) 51(-0.5,-20.7) 52(0.5,-20.7) 53(1.5,-20.7) 54(2.5,-20.7) 55(3.5,-20.7) 56(4.5,-20.7) 57(5.5,-20.7) 58(6.5,-20.7) 59(7.5,-20.7) 60(8.5,-20.7) 61(9.5,-20.7) 62(10.5,-20.7) 63(11.5,-20.7) 64(12.5,-20.7) 65(13.5,-20.7) 66(14.5,-20.7) 67(15.5,-20.7) 68(16.5,-20.7) 103(16.5,20.7) 104(15.5,20.7) 105(14.5,20.7) 106(13.5,20.7) 107(12.5,20.7) 108(11.5,20.7) 109(10.5,20.7) 110(9.5,20.7) 111(8.5,20.7) 112(7.5,20.7) 113(6.5,20.7) 114(5.5,20.7) 115(4.5,20.7) 116(3.5,20.7) 117(2.5,20.7) 118(1.5,20.7) 119(0.5,20.7) 120(-0.5,20.7) 121(-1.5,20.7) 122(-2.5,20.7) 123(-3.5,20.7) 124(-4.5,20.7) 125(-5.5,20.7) 126(-6.5,20.7) 127(-7.5,20.7) 128(-8.5,20.7) 129(-9.5,20.7) 130(-10.5,20.7) 131(-11.5,20.7) 132(-12.5,20.7) 133(-13.5,20.7) 134(-14.5,20.7) 135(-15.5,20.7) 136(-16.5,20.7)
  Keep-Out Layer lines w0.254: -17.2,-17.2 17.2,-17.2 17.2,17.2 -17.2,17.2 -17.2,-17.2
  silkscreen extent -22.27,-21.35 21.35,21.35
DC-IN-TH_DC-044A-20A [mm]
  oval 3x1.6 hole 1 slot 2.2 at 0 deg: 1(3.625,-4.5) 2(3.625,4) 3(3.625,-1.3) 4(-3.625,-4.9) 5(-3.625,4.9)
  Keep-Out Layer lines w0.127: -3.5,-2.15 -3.485,-2.165 -1.814,-2.165 -1.772,-2.123 -1.772,-0.478 -1.813,-0.437 -3.487,-0.437 -3.5,-0.45 -3.5,-2.15
  Keep-Out Layer lines w0.127: -3.906,-2.444 -3.906,-0.158 -1.366,-0.158 -1.366,-2.444 -3.906,-2.444
  silkscreen extent -6.7,-5.1 4.95,5
F1812 [mil]
  rect 55.38x137.76 smd: 1(-72.97,0) 2(72.97,0)
  silkscreen extent -142,-80 110,80
FPC-SMD_50P-P0.50_FPC-05FB-50PH20_MIRROR [mm]
  rect 0.3x1.2 smd paste+0 mask+0.05: 1(-12.25,1.625) 2(-11.75,1.625) 3(-11.25,1.625) 4(-10.75,1.625) 5(-10.25,1.625) 6(-9.75,1.625) 7(-9.25,1.625) 8(-8.75,1.625) 9(-8.25,1.625) 10(-7.75,1.625) 11(-7.25,1.625) 12(-6.75,1.625) 13(-6.25,1.625) 14(-5.75,1.625) 15(-5.25,1.625) 16(-4.75,1.625) 17(-4.25,1.625) 18(-3.75,1.625) 19(-3.25,1.625) 20(-2.75,1.625) 21(-2.25,1.625) 22(-1.75,1.625) 23(-1.25,1.625) 24(-0.75,1.625) 25(-0.25,1.625) 26(0.25,1.625) 27(0.75,1.625) 28(1.25,1.625) 29(1.75,1.625) 30(2.25,1.625) 31(2.75,1.625) 32(3.25,1.625) 33(3.75,1.625) 34(4.25,1.625) 35(4.75,1.625) 36(5.25,1.625) 37(5.75,1.625) 38(6.25,1.625) 39(6.75,1.625) 40(7.25,1.625) 41(7.75,1.625) 42(8.25,1.625) 43(8.75,1.625) 44(9.25,1.625) 45(9.75,1.625) 46(10.25,1.625) 47(10.75,1.625) 48(11.25,1.625) 49(11.75,1.625) 50(12.25,1.625)
  rect 2x1.8 smd paste+0 mask+0.05: 51(-13.8,-1.625) 52(13.8,-1.625)
  silkscreen extent -14.25,-3.88 14.25,2.13
HDR-SMD_40P-P2.54-V-M-R2-C20-LS7.5 [mm]
  rect 1.02x3.65 smd: 1(-24.13,-2.775) 2(-24.13,2.775) 3(-21.59,-2.775) 4(-21.59,2.775) 5(-19.05,-2.775) 6(-19.05,2.775) 7(-16.51,-2.775) 8(-16.51,2.775) 9(-13.97,-2.775) 10(-13.97,2.775) 11(-11.43,-2.775) 12(-11.43,2.775) 13(-8.89,-2.775) 14(-8.89,2.775) 15(-6.35,-2.775) 16(-6.35,2.775) 17(-3.81,-2.775) 18(-3.81,2.775) 19(-1.27,-2.775) 20(-1.27,2.775) 21(1.27,-2.775) 22(1.27,2.775) 23(3.81,-2.775) 24(3.81,2.775) 25(6.35,-2.775) 26(6.35,2.775) 27(8.89,-2.775) 28(8.89,2.775) 29(11.43,-2.775) 30(11.43,2.775) 31(13.97,-2.775) 32(13.97,2.775) 33(16.51,-2.775) 34(16.51,2.775) 35(19.05,-2.775) 36(19.05,2.775) 37(21.59,-2.775) 38(21.59,2.775) 39(24.13,-2.775) 40(24.13,2.775)
  silkscreen extent -25.6,-2.54 25.6,2.54
IND-SMD_L3.0-W3.0 [mm]
  rect 1.5x3.32 smd: 1(1.328,0) 2(-1.328,0)
  silkscreen extent -1.52,-1.91 1.52,1.9
IND-SMD_L4.0-W4.0 [mm]
  rect 1.6x3.5 smd: 1(-1.6,0) 2(1.6,0)
  silkscreen extent -2.08,-2.1 2.08,2.1
KEY-TH_TC-6615-6-160G [mm]
  round 1.5 hole 1: 1(2.25,-1.25) 2(-2.25,-1.25)
  round 2 hole 1.3: 3(-3.5,1.25) 4(3.5,1.25)
  silkscreen extent -3.8,-6.1 3.8,2.8
LED0402 [mm]
  rect 0.6x0.5 smd: 1(0.55,0) 2(-0.55,0)
  silkscreen extent -1.15,-0.45 1.05,0.45
OSC-SMD_4P-L2.5-W2.0-BL [mm]
  rect 1.2x1.1 smd mask+0.051: 1(-0.95,-0.75) 2(0.95,-0.75) 3(0.95,0.75) 4(-0.95,0.75)
  silkscreen extent -2.01,-1.76 1.78,1.53
RES-ARRAY-SMD_0402-8P-L2.0-W1.0-BL [mm]
  rect 0.3x0.505 smd: 1(-0.75,0.427) 2(-0.25,0.427) 3(0.25,0.427) 4(0.75,0.427) 5(0.75,-0.428) 6(0.25,-0.428) 7(-0.25,-0.428) 8(-0.75,-0.428)
  silkscreen extent -1.23,-0.91 1.23,0.91
SD-MR01A-01211 [mm]
  oval 0.7x1.8 smd mask+0.05: 1(2.35,7.4) 2(1.25,7.4) 3(0.15,7.4) 4(-0.95,7.4) 5(-2.05,7.4) 6(-3.15,7.4) 7(-4.25,7.4) 8(-5.35,7.4) 9(-6.45,7.4)
  rect 1.5x1.6 smd mask+0.05: 10(-7.9,6.9)
  rect 1.65x1.65 smd mask+0.05: 11(7.25,6.9)
  rect 1.8x2 smd mask+0.05: 12(-7.85,-2.7) 13(7.95,-2.7)
  round 1 hole 1 unplated: 14(3.15,-3.1) 15(-4.85,-3.1)
  silkscreen extent -7.6,-7.4 7.6,7.6
SOD-123_L2.8-W1.8-LS3.7-RD [mm]
  rect 1.2x1.4 smd: 1(1.7,0) 2(-1.7,0)
  silkscreen extent -1.5,-1 1.5,1
SOD-523_L1.2-W0.8-LS1.6-BI [mm]
  rect 0.6x0.6 smd: 1(-0.8,0) 2(0.8,0)
  silkscreen extent -0.65,-0.5 0.65,0.5
SOIC-8_L4.9-W3.9-P1.27-LS6.0-BL [mm]
  oval 0.588x2.045 smd: 1(-1.905,-2.773) 2(-0.635,-2.773) 3(0.635,-2.773) 4(1.905,-2.773) 5(1.905,2.773) 6(0.635,2.773) 7(-0.635,2.773) 8(-1.905,2.773)
  silkscreen extent -2.8,-2.92 2.53,1.52
SOT23 [mm] "SOT23, 3-Leads, Body 3.0x3.0mm (max), Pitch 0.95mm, IPC Medium Density"
  rect 1.1x0.6 smd: 1(-1.125,0.95) 2(-1.125,-0.95) 3(1.125,0)
  silkscreen extent 0.08,-1.5 0.88,1.5, body extent -0.87,-1.5 0.88,1.5, height 1.45
SOT-23-3_L2.9-W1.6-P1.90-LS2.8-BR [mm]
  rect 1.07x0.6 smd: 1(1.235,-0.95) 2(1.235,0.95) 3(-1.235,0)
  silkscreen extent -0.88,-1.54 0.88,1.54
SOT-23-5_L3.0-W1.7-P0.95-LS2.8-BL [mm]
  rect 0.49x1.157 smd: 1(-0.95,-1.154) 2(0,-1.154) 3(0.95,-1.154)
  rect 0.49x1.175 smd: 4(0.95,1.154) 5(-0.95,1.154)
  silkscreen extent -1.8,-1.29 1.53,0.85
SW-TH_4P-L4.5-W4.5-P3.00-LS5.5 [mm]
  round 1.6 hole 1 mask+0.051: 1(-2.75,1.5) 2(2.75,1.5) 3(-2.75,-1.5) 4(2.75,-1.5)
  silkscreen extent -2.25,-2.25 2.4,2.25
SW-TH_SS-12D11L3 [mm]
  round 2.5 hole 1.7: 1(-4.8,-4.6) 2(0,-4.6) 3(4.8,-4.6)
  round 2.5 hole 1.6: 4(-6.65,4.6) 5(6.65,4.6)
  silkscreen extent -6.76,-3.12 6.76,13.01
TP_1MM [mm]
  round 1 smd: 1(0,0)
TQFN-16_L3.0-W3.0-P0.50-BL-EP1.7 [mm]
  rect 0.25x0.75 smd paste-100 mask+0.051: 1(-0.748,-1.45) 2(-0.249,-1.45) 3(0.252,-1.45) 4(0.751,-1.45) 9(0.75,1.45) 10(0.25,1.45) 11(-0.25,1.45) 12(-0.749,1.45)
  rect 0.75x0.25 smd paste-100 mask+0.051: 5(1.45,-0.75) 6(1.45,-0.25) 7(1.45,0.25) 8(1.45,0.75) 13(-1.45,0.75) 14(-1.45,0.25) 15(-1.45,-0.25) 16(-1.45,-0.75)
  rect 1.7x1.7 smd paste-100 mask+0.051: 17(0,0)
  silkscreen extent -1.5,-2.17 1.5,1.5
TSOT-23-8 [mm]
  rect 1.2x0.4 smd: 1(-1.3,0.975) 2(-1.3,0.325) 3(-1.3,-0.325) 4(-1.3,-0.975) 5(1.3,-0.975) 6(1.3,-0.325) 7(1.3,0.325) 8(1.3,0.975)
  silkscreen extent -1.42,-1.5 0.3,1.8
"TYPEC-12PIN - duplicate" [mm]
  rect 0.6x1.44 smd mask+0.06: A1B12(-3.195,4.9) A4B9(-2.395,4.9) B1A12(3.205,4.9) B4A9(2.405,4.9)
  rect 0.3x1.44 smd mask+0.06: A5(-1.245,4.9) A6(-0.245,4.9) A7(0.255,4.9) A8(1.255,4.9) B5(1.755,4.9) B6(0.755,4.9) B7(-0.745,4.9) B8(-1.745,4.9)
  oval 1x2 hole 0.6 slot 1.2 at 90 deg mask+0.06: SHELL(-4.32,-0.025) SHELL(-4.32,4.18) SHELL(4.32,-0.008) SHELL(4.32,4.18)
  round 0.8 hole 0.8 unplated: ""(-2.888,3.68) ""(2.891,3.679)
  silkscreen extent -4.47,-2.61 4.47,4.79
USB-A-TH_C42425 [mm]
  rect 1x2.8 smd paste-100 mask+0.051: 1(-3.5,3.883) 2(-1,3.883) 3(1,3.883) 4(3.5,3.883)
  oval 1.5x2.8 hole 0.7 slot 1.7 at 90 deg: 5(6.4,-3.883) 6(-6.4,-3.883)
  silkscreen extent -6.55,-7 6.55,3.65
WQFN-40_L5.0-W5.0-P0.4-BL-EP [mm]
  oval 0.22x0.8 smd: 1(-1.801,-2.499) 2(-1.399,-2.499) 3(-1.001,-2.499) 4(-0.599,-2.499) 5(-0.201,-2.499) 6(0.201,-2.499) 7(0.6,-2.499) 8(1.001,-2.499) 9(1.4,-2.499) 10(1.801,-2.499) 21(1.801,2.499) 22(1.4,2.499) 23(1.001,2.499) 24(0.6,2.499) 25(0.201,2.499) 26(-0.201,2.499) 27(-0.599,2.499) 28(-1.001,2.499) 29(-1.399,2.499) 30(-1.801,2.499)
  oval 0.8x0.22 smd: 11(2.499,-1.801) 12(2.499,-1.4) 13(2.499,-1.001) 14(2.499,-0.6) 15(2.499,-0.201) 16(2.499,0.201) 17(2.499,0.599) 18(2.499,1.001) 19(2.499,1.399) 20(2.499,1.801) 31(-2.499,1.801) 32(-2.499,1.399) 33(-2.499,1.001) 34(-2.499,0.599) 35(-2.499,0.201) 36(-2.499,-0.201) 37(-2.499,-0.6) 38(-2.499,-1.001) 39(-2.499,-1.4) 40(-2.499,-1.801)
  rect 3.8x3.8 smd: 41(0,0)
  silkscreen extent -2.7,-3.35 2.7,2.7

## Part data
C1 C2 C3 C4 C5 C6 C7 C8 C9 C10 C11 C12 C13 C14 C15 C16 C17 C18 C19 C20 C21 C22 C23 C24 C25 C26 C27 C28 C29 C30 C33 C34 C35 C36 C37 C38 C39 C40 C42 C43 C44 C45 C46 C47 C48 C49 C50 C51 C52 C53 C54 C55 C56 C57 C58 C59 C60 C61 C62 C63 C64 C65 C66 C67 C68 C69 C70 C71 C72 C73 C74 C75 C76 C77: library part Cap, "Capacitor"
C31 C32 C41: library part 100uF
D1: library part "D Schottky", "Schottky Diode"
D23 D24: library part PESD1CAN_C343993
F1: library part SMD1812P014TF
HOST: library part JTJ-USB-AF-90-10.6X13.1-H5.7-002
J3: library part IDC40
J6 J7 J8 J9: library part KF2EDGR-3.5-2P
K1 K2 K3 K4: library part KEY_C174049
L1 L3: library part Inductor, "Inductor"
L2: library part 4.7uH
LED1: library part LED2, "Typical RED, GREEN, YELLOW, AMBER GaAs LED"
Q1: library part 1110505011
R1 R2 R3 R4 R5 R6 R7 R8 R9 R10 R11 R12 R13 R14 R15 R16 R17 R18 R19 R20 R21 R22 R23 R24 R25 R26 R27 R28 R29 R30 R31 R32 R33 R34 R35 R36 R37 R38 R39 R40 R41 R42 R43 R44 R45 R46 R47 R48 R49 R50 R51 R52 R53 R54 R55 R56 R57 R58 R59 R60 R61 R62 R63 R64 R65 R66 R67 R68 R69 R70 R71 R72 R73 R74 R75 R76 R77 R78 R79 R80 R81 R82 R83 R84 R85 R86 R87 R88 R89 R90 R91 R92 R93 R94 R95 R96 R97 R98 R99 R100 R101 R102 R103 R104 R105 R106 R130: library part Res1, "Resistor"
RN1 RN7: library part RES_ARRAY
TP1: library part TP
U3: library part XC6206
X3: library part 24MHz

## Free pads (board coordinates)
  round 236.22 hole 129.92: 0(157.48,236.22) 0(157.48,3110.24) 0(4055.12,236.22) 0(4055.12,3110.24)

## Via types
v1: diameter 17.72, hole 7.87, Top Layer to Bottom Layer, tented both sides, 571 vias

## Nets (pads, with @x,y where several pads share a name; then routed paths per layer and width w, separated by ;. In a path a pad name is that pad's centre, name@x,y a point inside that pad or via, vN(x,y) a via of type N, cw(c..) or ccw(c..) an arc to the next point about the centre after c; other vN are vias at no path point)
AP_CK24M_OUT: M1.37
AVCC: C15.1 C16.1 R13.2 R24.2 R66.2 U3.2 | length 5040.2
  Top Layer w20: R24.2@884.69,2797.48 960.37,2797.48 994.68,2763.16 C15.1@994.68,2662.52 ; C16.1@994.68,2617.52 C15.1@994.68,2662.52 ; U3.2@1052.6,2683.46 ccw(c1052.6,2711.6) 1072.49,2691.7 ; R66.2@3093.64,1535.27 ccw(c3068.03,1560.88) 3104.25,1560.88 ccw(c3140.46,1560.88) R66.2@3114.85,1535.27 ; R66.2@3104.25,1517.19 3104.25,1780.84 3104.25,1812.52 3213.52,1921.8 v1(3213.66,1921.8) ; v1(3238.02,2871.93) 3218.78,2891.17 3218.78,3003.2 3096.44,3125.53 1222.46,3125.53 1146.86,3049.93 1146.86,2766.07 U3.2@1052.6,2671.81 1043.31,2662.52 C15.1@994.68,2662.52 ; v1(3568.6,2898.72) 3647.19,2898.72 ; R13.2@3662.87,2860.03 ccw(c3609.32,2860.85) 3647.19,2898.72 ; R13.2@3664.69,2860 3664.69,2881.23 3647.19,2898.72
  Bottom Layer w20: v1@3213.74,1921.8 3213.74,2053.84 3238.02,2078.12 v1(3238.02,2871.93) 3264.82,2898.72 v1(3568.6,2898.72)
AVDD10: C74.1 C75.1 C76.1 R93.1 U9.3 U9.8 U9.38 | length 2285.2
  Top Layer w8: U9.38@3699.4,1572.86 3699.4,1529 3747.14,1481.26 C74.1@3850.32,1481.26 ; U9.3@3758.4,1631.86 3823.8,1631.86 v1(3824.04,1631.62) ; U9.8@3758.4,1710.66 3791.39,1710.66 3795.73,1715 v1(3823.93,1715) C75.1@3850.32,1715 ; 3806.36,1481.26 ccw(c3806.36,1495.58) v1@3816.48,1485.45 ; 3810.02,1481.26 cw(c3810.02,1472.12) v1@3816.48,1478.58 ; 3811.72,1631.86 cw(c3811.72,1619.29) v1@3820.61,1628.18 ; 3812.91,1631.86 ccw(c3812.91,1642.75) v1@3820.61,1635.05 ; v1@3820.49,1711.56 ccw(c3812.2,1703.27) 3812.2,1715 ccw(c3812.2,1726.73) v1@3820.49,1718.44 ; v1@3823.35,1478.58 cw(c3829.81,1472.12) 3829.81,1481.26 ; v1@3823.35,1485.45 ccw(c3833.48,1495.58) 3833.48,1481.26 ; v1@3826.47,1627.41 cw(c3832.74,1616.55) 3835.99,1628.66 ; v1@3826.92,1711.17 cw(c3834.46,1701.52) 3837.63,1713.35 ; v1@3826.92,1718.83 ccw(c3834.46,1728.48) 3837.63,1716.65 ; v1@3827.36,1711.56 cw(c3835.66,1703.27) 3835.66,1715 cw(c3835.66,1726.73) v1@3827.36,1718.44 ; v1@3827.48,1628.18 cw(c3836.37,1619.29) 3836.37,1631.86 ; v1@3827.48,1635.05 ccw(c3835.18,1642.75) 3835.18,1631.86 ; v1@3828.25,1634.05 ccw(c3837.7,1639.5) 3834.88,1628.96 ; C76.1@3844.2,1622.14 ccw(c3824.04,1606.11) 3824.04,1631.86 3849.71,1631.86 C76.1@3850.32,1631.26 ; C74.1@3844.79,1475.74 ccw(c3831.46,1462.4) 3831.46,1481.26 ccw(c3831.46,1500.12) C74.1@3844.79,1486.78 ; C75.1@3844.79,1709.48 ccw(c3831.46,1696.14) 3831.46,1715 ccw(c3831.46,1733.86) C75.1@3844.79,1720.52
  Top Layer w20: R93.1@3230,1568.82 3230,1599.88 v1(3230.12,1600) ; v1(3253.59,1135.39) 3639.84,1135.39 3666.65,1162.2 3795.86,1162.2 v1(3819.92,1186.26)
  Bottom Layer w20: v1(3230.12,1600) 3230.12,1238.36 3253.59,1214.89 v1(3253.59,1135.39) ; v1(3819.92,1186.26) v1(3819.92,1482.02) 3819.92,1506.07 3846.95,1533.11 3846.95,1575.72 3824.04,1598.63 v1@3824.04,1623.37 ; v1(3823.93,1715) 3823.93,1623.48 v1@3824.04,1623.37 ; v1(3824.04,1631.62) v1@3824.04,1623.37
AVDD33: C65.1 C68.1 R78.1 U9.11 U9.40 | length 1010.6
  Top Layer w8: 3730.9,1557.05 3740.87,1547.08 v1(3811.9,1547.08) ; U9.11@3730.9,1769.66 3730.9,1811.09 3820,1900.18 C68.1@3820,1921.57 ; U9.40@3731.23,1561.45 ccw(c3742.65,1561.45) 3734.58,1553.37 ; v1@3808.47,1543.65 ccw(c3800.17,1535.35) 3800.17,1547.08 ccw(c3800.17,1558.81) v1@3808.47,1550.52 ; C68.1@3814.48,1916.05 cw(c3801.14,1902.72) 3820,1902.72 cw(c3838.86,1902.72) C68.1@3825.52,1916.05
  Top Layer w15: 3843.07,1547.08 ccw(c3843.07,1567.04) C65.1@3858.67,1554.59 ; C65.1@3846.95,1563.95 cw(c3811.9,1591.92) v1(3811.9,1547.08) 3836.14,1547.08 C65.1@3850.32,1561.26
  Top Layer w20: C68.1@3820,1921.57 3867.87,1921.57 R78.1@3870,1923.7 3870.7,1924.4 v1(3904.57,1924.4) ; 3849.02,1921.57 ccw(c3849.02,1942.71) R78.1@3863.97,1927.77
  Bottom Layer w20: v1(3811.9,1547.08) 3796.55,1562.43 3796.55,1895.76 3825.19,1924.4 v1(3904.57,1924.4)
CAN0_H: D24.1 J8.2 R57.2 U7.7 | length 566.2
  Top Layer w10: U7.7@3514.15,980.63 R57.2@3603.39,980.63 3628.45,1005.69 3661.04,1005.69 3679.72,987.01 D24.1@3705.67,987.01 3705.67,995.03 3768.26,1057.63 J8.2@3900,1057.63 ; U7.7@3547.48,975.98 cw(c3558.71,964.76) 3558.71,980.63 cw(c3558.71,996.5) U7.7@3547.48,985.28 ; R57.2@3598.57,975.81 ccw(c3586.94,964.19) 3586.94,980.63 ccw(c3586.94,997.07) R57.2@3598.57,985.45 ; R57.2@3603.39,987.44 ccw(c3603.39,1003.88) 3615.01,992.26 ccw(c3626.64,980.63) R57.2@3610.2,980.63 ; D24.1@3700.85,982.2 ccw(c3689.23,970.57) 3689.23,987.01 ccw(c3689.23,1003.46) D24.1@3700.85,991.83 ; D24.1@3705.67,1003.08 ccw(c3705.67,1022.49) 3719.4,1008.76 ; D24.1@3712.48,996.26 cw(c3725.95,996.26) D24.1@3716.43,1005.79
CAN0_L: D24.2 J8.1 R56.1 U7.6 | length 625
  Top Layer w10: U7.6@3514.15,930.63 R56.1@3603.39,930.63 3626.59,907.43 3761.48,907.43 3780.47,926.43 D24.2@3780.47,987.01 3820.61,987.01 J8.1@3900,907.62 ; U7.6@3547.48,925.98 cw(c3558.71,914.76) 3558.71,930.63 cw(c3558.71,946.5) U7.6@3547.48,935.28 ; R56.1@3598.57,925.81 ccw(c3586.94,914.19) 3586.94,930.63 ccw(c3586.94,947.07) R56.1@3598.57,935.45 ; R56.1@3603.39,923.82 cw(c3603.39,907.38) 3615.01,919 cw(c3626.64,930.63) R56.1@3610.2,930.63 ; D24.2@3775.66,972.94 cw(c3764.03,961.32) 3780.47,961.32 cw(c3796.92,961.32) D24.2@3785.29,972.94 ; D24.2@3785.29,982.2 cw(c3796.92,970.57) 3796.92,987.01 cw(c3796.92,1003.46) D24.2@3785.29,991.83
CAN0_RX: M1.93 R47.2 | length 1615.7
  Top Layer w6: M1.93@2867.13,2060.24 v1@2999.07,2060.24 ; M1.93@2890.5,2052.61 cw(c2908.9,2034.21) 2908.9,2060.24 cw(c2908.9,2086.26) M1.93@2890.5,2067.86 ; 2984.9,2060.24 ccw(c2984.9,2074.44) v1@2994.95,2064.4 ; 2984.99,2060.24 cw(c2984.99,2046.16) v1@2994.95,2056.11 ; v1(3061.5,898.74) 3061.6,898.63 3132.31,898.63 R47.2@3150.31,880.63 ; v1@3065.64,894.6 cw(c3075.38,884.85) 3075.38,898.63 ; v1@3065.64,902.88 ccw(c3075.9,913.14) 3075.9,898.63 ; R47.2@3141.5,880.63 ccw(c3120.23,880.63) 3135.27,895.67 ccw(c3150.31,910.71) R47.2@3150.31,889.44
  Bottom Layer w6: v1(2999.09,2060.25) 3025.65,2060.25 3035.59,2050.32 3035.59,1257.51 3019.57,1241.5 3019.57,1109.98 3071.44,1058.11 3071.44,908.68 ; v1@3003.23,2056.11 cw(c3013.23,2046.11) 3013.23,2060.25 cw(c3013.23,2074.4) v1@3003.23,2064.4 ; v1(3061.5,898.74) 3071.44,908.68 ; v1@3061.52,904.6 ccw(c3061.58,918.54) 3071.44,908.68 ; v1@3067.36,898.76 cw(c3081.3,898.82) 3071.44,908.68
CAN0_TX: M1.92 R48.2 | length 1424.6
  Top Layer w6: M1.92@2867.13,2020.87 v1(2984.52,2020.84) ; M1.92@2890.5,2013.24 cw(c2908.9,1994.84) 2908.9,2020.87 cw(c2908.9,2046.89) M1.92@2890.5,2028.49 ; 2970.31,2020.87 cw(c2970.31,2006.62) v1@2980.38,2016.69 ; 2970.45,2020.87 ccw(c2970.45,2034.91) v1@2980.38,2024.98 ; v1(3050.05,1031.51) 3150.07,1031.51 R48.2@3150.31,1031.26 ; v1@3054.19,1027.36 cw(c3064.19,1017.36) 3064.19,1031.51 cw(c3064.19,1045.65) v1@3054.19,1035.65 ; 3128.45,1031.51 cw(c3128.45,1009.39) R48.2@3144.08,1025.03 ; 3129.64,1031.51 ccw(c3129.64,1051.93) R48.2@3144.08,1037.49
  Bottom Layer w6: v1(2984.52,2020.84) 3008,2020.84 3023.59,2005.25 3023.59,1262.48 3007.32,1246.21 3007.32,1104.6 3050.05,1061.86 v1(3050.05,1031.51) ; v1@2988.66,2016.69 cw(c2998.66,2006.69) 2998.66,2020.84 cw(c2998.66,2034.98) v1@2988.66,2024.98 ; v1@3045.91,1035.65 ccw(c3035.91,1045.65) 3050.05,1045.65 ccw(c3064.19,1045.65) v1@3054.19,1035.65
CAN1_H: D23.1 J7.2 R55.2 U6.7 | length 559.1
  Top Layer w10: U6.7@3514.15,600.63 R55.2@3603.39,600.63 3628.9,626.14 3662.06,626.14 3676.82,611.38 D23.1@3705.67,611.38 3705.67,623.35 3735.02,652.7 3889.92,652.7 J7.2@3900,642.63 ; U6.7@3547.48,595.98 cw(c3558.71,584.76) 3558.71,600.63 cw(c3558.71,616.5) U6.7@3547.48,605.28 ; R55.2@3598.57,595.81 ccw(c3586.94,584.19) 3586.94,600.63 ccw(c3586.94,617.07) R55.2@3598.57,605.45 ; R55.2@3603.39,607.44 ccw(c3603.39,623.88) 3615.01,612.26 ccw(c3626.64,600.63) R55.2@3610.2,600.63 ; D23.1@3700.85,606.57 ccw(c3689.23,594.94) 3689.23,611.38 ccw(c3689.23,627.83) D23.1@3700.85,616.2 ; D23.1@3705.67,627.45 ccw(c3705.67,637.34) D23.1@3712.66,630.34 ; D23.1@3712.48,620.63 cw(c3735.47,620.63) 3719.21,636.89
CAN1_L: D23.2 J7.1 R54.1 U6.6 | length 658.7
  Top Layer w10: U6.6@3514.15,550.63 R54.1@3603.39,550.63 3626.36,527.65 3752.65,527.65 3780.47,555.47 D23.2@3780.47,611.38 3812.67,611.38 3827.95,596.11 3827.95,564.68 J7.1@3900,492.62 ; U6.6@3547.48,545.98 cw(c3558.71,534.76) 3558.71,550.63 cw(c3558.71,566.5) U6.6@3547.48,555.28 ; R54.1@3598.57,545.81 ccw(c3586.94,534.19) 3586.94,550.63 ccw(c3586.94,567.07) R54.1@3598.57,555.45 ; R54.1@3603.39,543.82 cw(c3603.39,527.38) 3615.01,539 cw(c3626.64,550.63) R54.1@3610.2,550.63 ; D23.2@3775.66,597.31 cw(c3764.03,585.69) 3780.47,585.69 cw(c3796.92,585.69) D23.2@3785.29,597.31 ; D23.2@3785.29,606.57 cw(c3796.92,594.94) 3796.92,611.38 cw(c3796.92,627.83) D23.2@3785.29,616.2
CAN1_RX: M1.94 R45.2 | length 2017.6
  Top Layer w6: M1.94@2867.13,2099.61 v1@3000.27,2099.61 ; M1.94@2890.5,2091.98 cw(c2908.9,2073.58) 2908.9,2099.61 cw(c2908.9,2125.63) M1.94@2890.5,2107.23 ; v1@2996.13,2095.46 ccw(c2986.12,2085.45) 2986.12,2099.61 ccw(c2986.14,2113.74) v1@2996.13,2103.75 ; v1(3099.19,501.04) 3099.41,501.26 R45.2@3150.31,501.26 ; v1@3103.33,496.9 cw(c3113.86,486.37) 3113.86,501.26 ; v1@3103.33,505.18 ccw(c3112.81,514.66) 3112.81,501.26 ; R45.2@3144.08,495.03 ccw(c3129.04,479.99) 3129.04,501.26 ccw(c3129.04,522.53) R45.2@3144.08,507.49
  Bottom Layer w6: v1(3000.27,2099.6) 3030.06,2099.6 3047.59,2082.07 3047.59,1252.54 3031.72,1236.68 3031.72,1115.13 3083.44,1063.41 3083.44,516.79 v1(3099.19,501.04) ; v1@3004.42,2095.46 cw(c3014.42,2085.46) 3014.42,2099.6 cw(c3014.42,2113.75) v1@3004.42,2103.75 ; v1@3093.33,501.04 ccw(c3079.19,501.04) 3089.19,511.04 ccw(c3099.19,521.04) v1@3099.19,506.9
CAN1_TX: M1.96 R46.2 | length 1932.1
  Top Layer w6: M1.96@2867.13,2178.35 2986.72,2178.35 v1(2986.88,2178.18) ; M1.96@2890.5,2170.72 cw(c2908.9,2152.32) 2908.9,2178.35 cw(c2908.9,2204.37) M1.96@2890.5,2185.97 ; 2972.34,2178.35 cw(c2972.34,2163.65) v1@2982.74,2174.04 ; 2973.13,2178.35 ccw(c2973.13,2191.93) v1@2982.74,2182.33 ; v1(3107.89,651.43) 3150.14,651.43 R46.2@3150.31,651.26 ; v1@3112.03,647.29 cw(c3122.03,637.29) 3122.03,651.43 cw(c3122.03,665.58) v1@3112.03,655.58 ; 3128.63,651.43 cw(c3128.63,629.57) R46.2@3144.08,645.03 ; 3129.46,651.43 ccw(c3129.46,672.11) R46.2@3144.08,657.49
  Bottom Layer w6: v1(2986.88,2178.18) 3015.39,2178.18 3059.59,2133.99 3059.59,1247.57 3043.87,1231.85 3043.87,1120.05 3095.44,1068.48 3095.44,663.88 v1(3107.89,651.43) ; v1@2991.02,2174.04 cw(c3001.02,2164.04) 3001.02,2178.18 cw(c3001.02,2192.33) v1@2991.02,2182.33 ; v1@3102.03,651.43 ccw(c3087.89,651.43) 3097.89,661.43 ccw(c3107.89,671.43) v1@3107.89,657.29
CH343P_RXD: D14.1 R36.2 U4.5 | length 315.5
  Top Layer w6: R36.2@2080.35,576.22 2104.11,552.46 2178.41,552.46 D14.1@2202.17,576.22 2249.17,623.23 U4.5@2289.91,623.23 ; D14.1@2193.35,576.22 cw(c2172.08,576.22) 2187.12,561.18 cw(c2202.17,546.14) D14.1@2202.17,567.41 ; D14.1@2202.17,585.03 ccw(c2202.17,606.3) 2217.21,591.26 ccw(c2232.25,576.22) D14.1@2210.98,576.22
CH343P_TXD: D13.1 Q1.3 U4.4 | length 448.5
  Top Layer w6: Q1.3@1950,595.71 1952.77,592.94 2101.99,592.94 2110.05,601.01 2176.95,601.01 D13.1@2202.17,626.22 2227.59,626.22 2252.09,650.73 U4.4@2256.01,650.73 ; Q1.3@1951.99,597.7 ccw(c1963.47,609.17) 1963.47,592.94 ; Q1.3@1956.23,589.48 cw(c1964.59,581.12) 1964.59,592.94 ; Q1.3@1956.23,601.94 ccw(c1977.95,623.66) 1977.95,592.94 ; D13.1@2193.35,626.22 cw(c2172.08,626.22) 2187.12,611.18 cw(c2202.17,596.14) D13.1@2202.17,617.41 ; D13.1@2208.4,619.99 cw(c2223.44,604.95) 2223.44,626.22 cw(c2223.44,647.49) D13.1@2208.4,632.45 ; U4.4@2248.53,647.16 cw(c2252.5,643.19) U4.4@2252.5,648.81
CLKOUT_125M: R68.1 U9.35 | length 144.3
  Top Layer w6: R68.1@3648.77,1482.18 ccw(c3640.72,1490.22) 3652.1,1490.22 ; R68.1@3650,1475.94 3652.1,1478.05 U9.35@3652.1,1572.86 ; 3652.1,1489.73 ccw(c3668.78,1489.73) R68.1@3656.99,1477.93 ; 3652.1,1504.21 ccw(c3683.27,1504.21) R68.1@3661.23,1482.18
CTP_INT: J1.35 M1.103 | length 1317.8
  Top Layer w6: v1@1915.09,2866.32 ccw(c1904.95,2876.46) 1919.29,2876.46 ; J1.35@1917.24,3031.25 cw(c1912.28,3026.29) 1919.29,3026.29 cw(c1926.31,3026.29) J1.35@1921.35,3031.25 ; v1(1919.12,2771.03) 1932.54,2771.03 ; v1(1919.23,2862.17) 1919.29,2862.24 J1.35@1919.29,3051.03 ; 1919.29,2876.17 ccw(c1933.23,2876.17) v1@1923.38,2866.32 ; v1@1923.41,2767.05 cw(c1932.54,2758.59) 1932.54,2771.03 ; v1@1923.41,2775.01 ccw(c1932.54,2783.48) 1932.54,2771.03 ; M1.103@2694.15,2603.29 ccw(c2675.75,2621.69) 2701.77,2621.69 ccw(c2727.8,2621.69) M1.103@2709.39,2603.29 ; M1.103@2701.77,2579.92 2701.77,2633.43 2674.28,2660.92 2206.65,2660.92 2089.82,2777.76 1939.26,2777.76 1932.54,2771.03
  Bottom Layer w6: v1@1914.97,2775.17 ccw(c1904.68,2785.46) 1919.23,2785.46 ; v1@1915.09,2858.03 cw(c1905.09,2848.03) 1919.23,2848.03 cw(c1933.38,2848.03) v1@1923.38,2858.03 ; v1@1919.23,2771.03 v1(1919.23,2862.17) ; 1919.23,2784.89 ccw(c1932.97,2784.89) v1@1923.26,2775.17
CTP_RST: J1.36 M1.41 | length 3073.2
  Top Layer w6: M1.41@1631.16,926.63 cw(c1614.3,909.77) v1@1638.14,909.77 ; v1@1633.41,909.52 ccw(c1623.34,916.86) 1635.38,920.09 ; v1@1634,910.21 ccw(c1624,920.21) 1638.14,920.21 ccw(c1652.28,920.21) v1@1642.28,910.21 ; v1@1635.21,911.14 ccw(c1628.41,922.92) 1641.55,919.4 ; 1636,917.75 ccw(c1646.51,920.56) v1@1641.07,911.14 ; v1(1638.14,906.07) 1638.14,949.36 M1.41@1638.78,950 ; v1@1638.14,906.69 cw(c1666.34,906.69) M1.41@1646.4,926.63 ; 1641.75,920.14 ccw(c1655.93,916.34) v1@1643.21,909 ; v1@1895.18,2849.49 ccw(c1884.5,2860.17) 1899.6,2860.17 ; J1.36@1897.55,3031.25 cw(c1892.59,3026.29) 1899.6,3026.29 cw(c1906.62,3026.29) J1.36@1901.66,3031.25 ; v1(1899.32,2845.34) 1899.6,2845.63 J1.36@1899.6,3051.03 ; 1899.6,2858.81 ccw(c1912.78,2858.81) v1@1903.46,2849.49
  Bottom Layer w6: v1@1632.28,906.07 cw(c1618.14,906.07) 1628.14,896.07 cw(c1638.14,886.07) v1@1638.14,900.21 ; v1(1638.14,906.07) 1620.17,888.09 1588.78,888.09 1583.18,893.7 1403,893.7 1340.33,956.36 1340.33,2458.51 1370.81,2488.99 1547.6,2488.99 1737.28,2678.67 1878.91,2678.67 1899.32,2699.08 v1(1899.32,2845.34) ; v1@1895.18,2841.2 cw(c1885.18,2831.2) 1899.32,2831.2 cw(c1913.46,2831.2) v1@1903.46,2841.2
DEBUG_DM: D5.2 DEBUG.A7 DEBUG.B7 U4.8 | length 446.8
  Top Layer w9.53: DEBUG.B7@2308.67,374.13 2308.67,333.93 2315.61,326.99 2339.78,326.99 2348.04,335.26 DEBUG.A7@2348.04,374.13 2348.04,439.76 D5.2@2368,459.72 2344.95,482.78 2344.95,596.28 2348.96,600.3 U4.8@2348.96,623.23 ; D5.2@2368,452.68 ccw(c2368,435.67) 2355.97,447.7 ccw(c2343.94,459.72) 2360.95,459.72 ccw(c2343.94,459.72) 2355.97,471.75 ccw(c2368,483.78) D5.2@2368,466.77
DEBUG_DP: D7.2 DEBUG.A6 DEBUG.B6 U4.7 | length 482.3
  Top Layer w9.53: D7.2@2305,452.68 cw(c2305,435.67) 2317.03,447.7 cw(c2329.06,459.72) 2312.05,459.72 cw(c2329.06,459.72) 2317.03,471.75 cw(c2305,483.78) D7.2@2305,466.77 ; D7.2@2305,459.72 2328.35,436.37 v1(2328.35,425.36) DEBUG.A6@2328.35,374.13 ; D7.2@2311.7,466.43 2329.42,484.14 2329.42,623.09 U4.7@2329.28,623.23 ; v1@2325.46,422.46 cw(c2318.47,415.48) 2328.35,415.48 cw(c2338.24,415.48) v1@2331.25,422.46 ; v1@2325.46,428.25 ccw(c2318.47,435.24) 2328.35,435.24 ccw(c2338.24,435.24) v1@2331.25,428.25 ; v1@2365.73,422.37 cw(c2358.74,415.38) 2368.62,415.38 cw(c2378.51,415.38) v1@2371.52,422.37 ; DEBUG.B6@2367.72,374.13 2368.62,375.03 v1(2368.62,425.26)
  Bottom Layer w9.53: v1(2328.35,425.36) 2368.53,425.36 v1(2368.62,425.26) ; v1@2331.25,422.46 cw(c2338.24,415.48) 2338.24,425.36 cw(c2338.24,435.24) v1@2331.25,428.25 ; 2358.51,425.36 cw(c2358.51,415.15) v1@2365.73,422.37 ; 2358.97,425.36 ccw(c2358.97,434.91) v1@2365.73,428.16
DM_P0: D16.2 OTG.A7 OTG.B7 R39.1 | length 449.5
  Top Layer w9.53: OTG.B7@1695.04,374.13 1695.04,334.97 1705.09,324.92 1726.51,324.92 1734.41,332.82 OTG.A7@1734.41,374.13 1734.41,445.91 D16.2@1757,468.5 1733.53,491.98 1733.53,573.84 R39.1@1750,590.32 ; R39.1@1742.95,590.32 cw(c1725.94,590.32) 1737.97,578.29 cw(c1750,566.26) R39.1@1750,583.27 ; D16.2@1757,461.46 ccw(c1757,444.45) 1744.97,456.48 ccw(c1732.94,468.5) 1749.95,468.5 ccw(c1732.94,468.5) 1744.97,480.53 ccw(c1757,492.56) D16.2@1757,475.55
